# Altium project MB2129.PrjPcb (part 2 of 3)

## Sheet Connectors.SchDoc: Connectors
size A3; Date: Not used; ApprovedBy: Not used; CheckedBy: Not used; Author: Not used; CompanyName: STMicroelectronics; DrawnBy: Not used; Engineer: Not used; Organization: Not used; Address1: Not used; Address2: Not used; Address3: Not used; Address4: Not used; DocumentNumber: 5; Revision: Not used; SheetNumber: 5; SheetTotal: 14
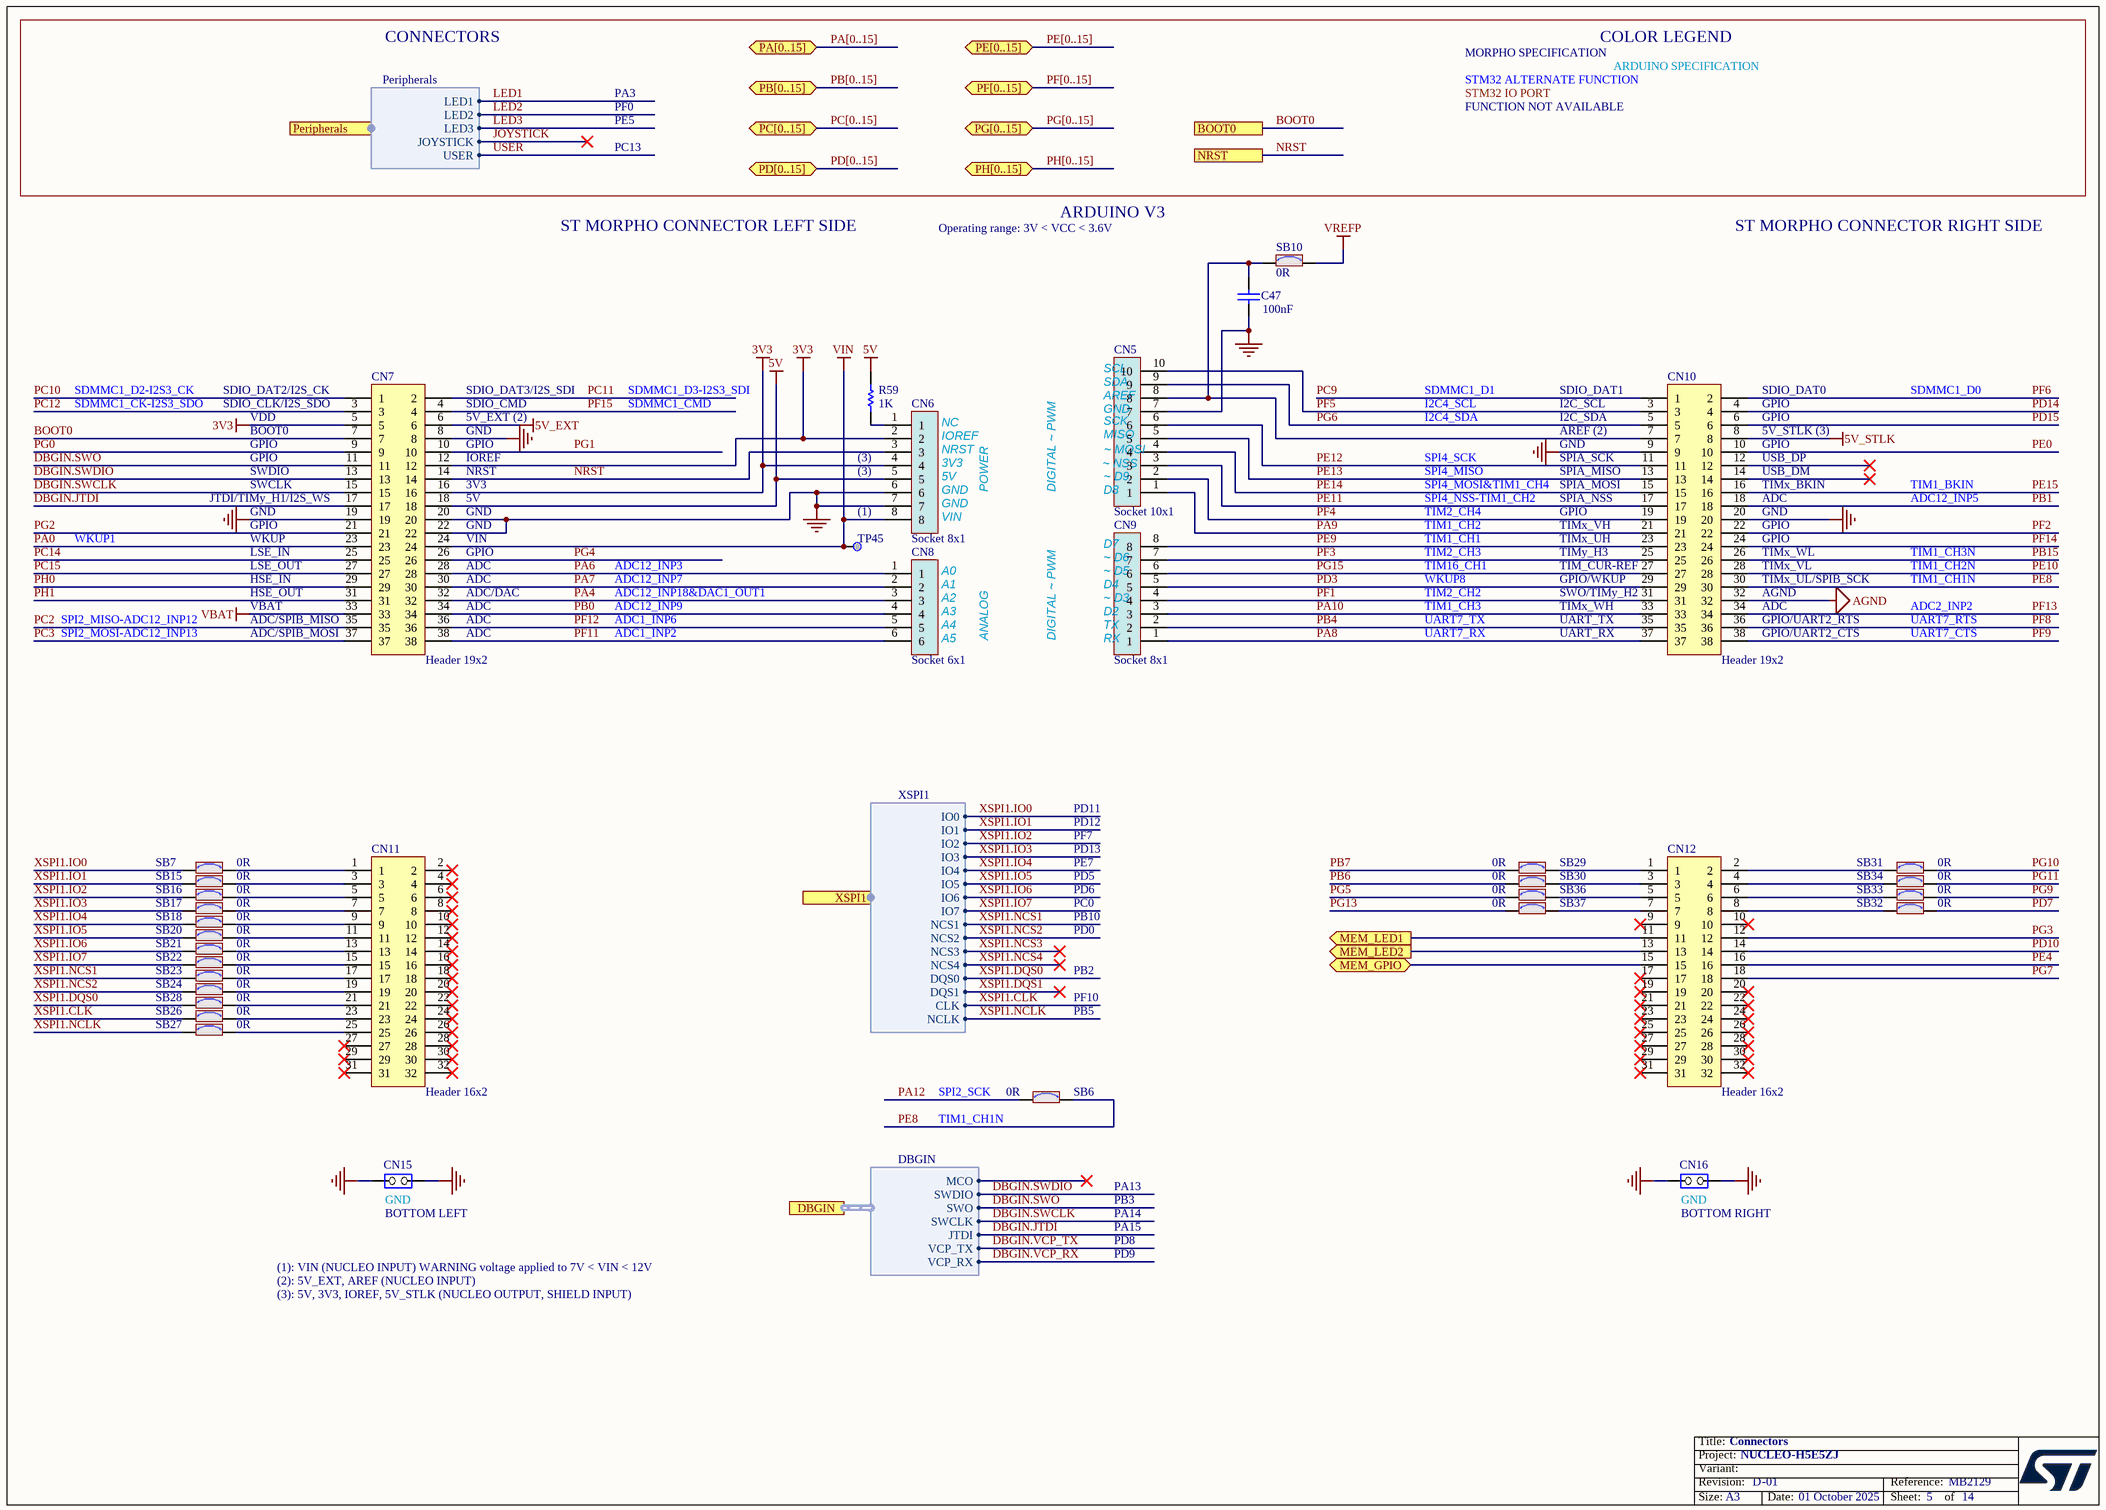
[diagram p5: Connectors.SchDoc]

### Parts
C47  value 100nF  [C0402]  (hidden comment: Capacitor)
CN5  Socket 10x1  [CON_SAMTEC_SSW-110-01-X-S]
CN6  Socket 8x1  [CON_SAMTEC_SSW-108-01-X-S]
CN7  Header 19x2  [CON_SAMTEC_TSW-119-09-X-D]
CN8  Socket 6x1  [CON_SAMTEC_SSW-106-01-X-S]
CN9  Socket 8x1  [CON_SAMTEC_SSW-108-01-X-S]
CN10  Header 19x2  [CON_SAMTEC_TSW-119-09-X-D]
CN11  Header 16x2  [CON_SAMTEC_TSW-116-07-G-D]
CN12  Header 16x2  [CON_SAMTEC_TSW-116-07-G-D]
CN15  Jumper_Header 2x1  [CON_SAMTEC_TSW-102-09-X-S]  (value not drawn)
CN16  Jumper_Header 2x1  [CON_SAMTEC_TSW-102-09-X-S]  (value not drawn)
R59  value 1K  [R0402]  (hidden comment: Resistor)
SB6  value 0R  [SOLDER-BRIDGE_R0603-0R]  (hidden comment: SB_ON)
SB7  value 0R  [SOLDER-BRIDGE_R0603-0R]  (hidden comment: SB_ON)
SB10  value 0R  [SOLDER-BRIDGE_R0402-0R]  (hidden comment: SB_ON)
SB15  value 0R  [SOLDER-BRIDGE_R0603-0R]  (hidden comment: SB_ON)
SB16  value 0R  [SOLDER-BRIDGE_R0603-0R]  (hidden comment: SB_ON)
SB17  value 0R  [SOLDER-BRIDGE_R0603-0R]  (hidden comment: SB_ON)
SB18  value 0R  [SOLDER-BRIDGE_R0603-0R]  (hidden comment: SB_ON)
SB20  value 0R  [SOLDER-BRIDGE_R0603-0R]  (hidden comment: SB_ON)
SB21  value 0R  [SOLDER-BRIDGE_R0603-0R]  (hidden comment: SB_ON)
SB22  value 0R  [SOLDER-BRIDGE_R0603-0R]  (hidden comment: SB_ON)
SB23  value 0R  [SOLDER-BRIDGE_R0603-0R]  (hidden comment: SB_ON)
SB24  value 0R  [SOLDER-BRIDGE_R0603-0R]  (hidden comment: SB_ON)
SB26  value 0R  [SOLDER-BRIDGE_R0603-0R]  (hidden comment: SB_ON)
SB27  value 0R  [SOLDER-BRIDGE_R0603-0R]  (hidden comment: SB_ON)
SB28  value 0R  [SOLDER-BRIDGE_R0603-0R]  (hidden comment: SB_ON)
SB29  value 0R  [SOLDER-BRIDGE_R0603-0R]  (hidden comment: SB_ON)
SB30  value 0R  [SOLDER-BRIDGE_R0603-0R]  (hidden comment: SB_ON)
SB31  value 0R  [SOLDER-BRIDGE_R0603-0R]  (hidden comment: SB_ON)
SB32  value 0R  [SOLDER-BRIDGE_R0603-0R]  (hidden comment: SB_ON)
SB33  value 0R  [SOLDER-BRIDGE_R0603-0R]  (hidden comment: SB_ON)
SB34  value 0R  [SOLDER-BRIDGE_R0603-0R]  (hidden comment: SB_ON)
SB36  value 0R  [SOLDER-BRIDGE_R0603-0R]  (hidden comment: SB_ON)
SB37  value 0R  [SOLDER-BRIDGE_R0603-0R]  (hidden comment: SB_ON)
TP45  Test Point  [TP_SMD_0-6MM]  (value not drawn)  (no BOM)

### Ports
BOOT0, DBGIN (harness DBGIN), MEM_GPIO (bidir), MEM_LED1 (out), MEM_LED2 (out), NRST, PA[0..15] (bidir), PB[0..15] (bidir), PC[0..15] (bidir), PD[0..15] (bidir), PE[0..15] (bidir), Peripherals (harness Peripherals), PF[0..15] (bidir), PG[0..15] (bidir), PH[0..15] (bidir), XSPI1 (harness XSPI1)

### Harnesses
Peripherals: LED1, LED2, USER, LED3, JOYSTICK
XSPI1: IO0, IO1, IO2, IO3, IO4, IO5, IO6, IO7, NCS1, NCS2, DQS0, CLK, NCLK, NCS3, NCS4, DQS1
DBGIN: SWDIO, SWO, VCP_TX, SWCLK, VCP_RX, MCO, JTDI

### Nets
3V3: CN6.2 CN6.4 CN7.5 CN7.12 CN7.16
5V: CN6.5 CN7.18 R59.2
5V_EXT: CN7.6
5V_STLK: CN10.8
AGND: CN10.32
GND: C47.2 CN5.7 CN6.6 CN6.7 CN7.8 CN7.19 CN7.20 CN7.22 CN10.9 CN10.20 CN15.1(COMMON) CN15.2(NO) CN16.1(COMMON) CN16.2(NO)
VBAT: CN7.33
VIN: CN6.8 CN7.24 TP45.1
VREFP: SB10.1
BOOT0: CN7.7 ; port BOOT0
DBGIN.JTDI: CN7.17 ; port DBGIN.JTDI
DBGIN.SWCLK: CN7.15 ; port DBGIN.SWCLK
DBGIN.SWDIO: CN7.13 ; port DBGIN.SWDIO
DBGIN.SWO: CN7.11 ; port DBGIN.SWO
MEM_GPIO: CN12.15 ; port MEM_GPIO
MEM_LED1: CN12.11 ; port MEM_LED1
MEM_LED2: CN12.13 ; port MEM_LED2
NRST: CN6.3 CN7.14 ; port NRST
PA0: CN7.23
PA4: CN7.32 CN8.3
PA6: CN7.28 CN8.1
PA7: CN7.30 CN8.2
PA8: CN9.1 CN10.37
PA9: CN5.1 CN10.21
PA10: CN9.3 CN10.33
PA12: SB6.1
PB0: CN7.34 CN8.4
PB1: CN10.18
PB4: CN9.2 CN10.35
PB6: SB30.1
PB7: SB29.1
PB15: CN10.26
PC2: CN7.35
PC3: CN7.37
PC9: CN10.1
PC10: CN7.1
PC11: CN7.2
PC12: CN7.3
PC14: CN7.25
PC15: CN7.27
PD3: CN9.5 CN10.29
PD7: SB32.1
PD10: CN12.14
PD14: CN10.4
PD15: CN10.6
PE0: CN10.10
PE4: CN12.16
PE8: CN10.30 SB6.2
PE9: CN9.8 CN10.23
PE10: CN10.28
PE11: CN5.3 CN10.17
PE12: CN5.6 CN10.11
PE13: CN5.5 CN10.13
PE14: CN5.4 CN10.15
PE15: CN10.16
PF1: CN9.4 CN10.31
PF2: CN10.22
PF3: CN9.7 CN10.25
PF4: CN5.2 CN10.19
PF5: CN5.10 CN10.3
PF6: CN10.2
PF8: CN10.36
PF9: CN10.38
PF11: CN7.38 CN8.6
PF12: CN7.36 CN8.5
PF13: CN10.34
PF14: CN10.24
PF15: CN7.4
PG0: CN7.9
PG1: CN7.10
PG2: CN7.21
PG3: CN12.12
PG4: CN7.26
PG5: SB36.1
PG6: CN5.9 CN10.5
PG7: CN12.18
PG9: SB33.1
PG10: SB31.1
PG11: SB34.1
PG13: SB37.1
PG15: CN9.6 CN10.27
PH0: CN7.29
PH1: CN7.31
XSPI1.CLK: SB26.1 ; port XSPI1.CLK
XSPI1.DQS0: SB28.1 ; port XSPI1.DQS0
XSPI1.IO0: SB7.1 ; port XSPI1.IO0
XSPI1.IO1: SB15.1 ; port XSPI1.IO1
XSPI1.IO2: SB16.1 ; port XSPI1.IO2
XSPI1.IO3: SB17.1 ; port XSPI1.IO3
XSPI1.IO4: SB18.1 ; port XSPI1.IO4
XSPI1.IO5: SB20.1 ; port XSPI1.IO5
XSPI1.IO6: SB21.1 ; port XSPI1.IO6
XSPI1.IO7: SB22.1 ; port XSPI1.IO7
XSPI1.NCLK: SB27.1 ; port XSPI1.NCLK
XSPI1.NCS1: SB23.1 ; port XSPI1.NCS1
XSPI1.NCS2: SB24.1 ; port XSPI1.NCS2
NetC47_1: C47.1 CN5.8 CN10.7 SB10.2
NetCN6_1: CN6.1 R59.1
NetCN11_1: CN11.1 SB7.2
NetCN11_3: CN11.3 SB15.2
NetCN11_5: CN11.5 SB16.2
NetCN11_7: CN11.7 SB17.2
NetCN11_9: CN11.9 SB18.2
NetCN11_11: CN11.11 SB20.2
NetCN11_13: CN11.13 SB21.2
NetCN11_15: CN11.15 SB22.2
NetCN11_17: CN11.17 SB23.2
NetCN11_19: CN11.19 SB24.2
NetCN11_21: CN11.21 SB28.2
NetCN11_23: CN11.23 SB26.2
NetCN11_25: CN11.25 SB27.2
NetCN12_1: CN12.1 SB29.2
NetCN12_2: CN12.2 SB31.2
NetCN12_3: CN12.3 SB30.2
NetCN12_4: CN12.4 SB34.2
NetCN12_5: CN12.5 SB36.2
NetCN12_6: CN12.6 SB33.2
NetCN12_7: CN12.7 SB37.2
NetCN12_8: CN12.8 SB32.2

Not connected (* = marked no-connect by the designer): CN10 12* 14*; CN11 2* 4* 6* 8* 10* 12* 14* 16* 18* 20* 22* 24* 26* 27* 28* 29* 30* 31* 32*; CN12 9* 10* 17* 19* 20* 21* 22* 23* 24* 25* 26* 27* 28* 29* 30* 31* 32*

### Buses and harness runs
bus PA[0..15] = port PA[0..15]
bus PB[0..15] = port PB[0..15]
bus PC[0..15] = port PC[0..15]
bus PD[0..15] = port PD[0..15]
bus PE[0..15] = port PE[0..15]
bus PF[0..15] = port PF[0..15]
bus PG[0..15] = port PG[0..15]
bus PH[0..15] = port PH[0..15]

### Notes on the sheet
- CONNECTORS
- COLOR LEGEND
- PA3
- PF0
- MORPHO SPECIFICATION
- STM32 ALTERNATE FUNCTION
- STM32 IO PORT
- FUNCTION NOT AVAILABLE
- ARDUINO SPECIFICATION
- PE5
- PC13
- ST MORPHO CONNECTOR LEFT SIDE
- Operating range: 3V < VCC < 3.6V
- ARDUINO V3
- ST MORPHO CONNECTOR RIGHT SIDE
- (near CN5) SDA
- (near CN5) SCL
- SDMMC1_CK-I2S3_SDO
- SDMMC1_D2-I2S3_CK
- (near CN7) SDIO_DAT2/I2S_CK
- (near CN7) SDIO_CLK/I2S_SDO
- BOOT0
- GPIO
- VDD
- (near CN7) SDIO_CMD
- (near CN7) GPIO
- (near CN7) 5V_EXT (2)
- (near CN7) GND
- (near CN7) SDIO_DAT3/I2S_SDI
- SDMMC1_CMD
- SDMMC1_D3-I2S3_SDI
- (near CN6) IOREF
- (near CN6) NRST
- (near CN6) NC
- (near CN5) SCK
- (near CN5) MISO
- (near CN5) AREF
- (near CN5) GND
- (near CN5) ~ MOSI
- I2C4_SDA
- I2C4_SCL
- SDMMC1_D1
- (near CN10) SDIO_DAT1
- I2C_SCL
- I2C_SDA
- AREF (2)
- GND
- (near CN10) SDIO_DAT0
- (near CN10) GPIO
- (near CN10) 5V_STLK (3)
- SDMMC1_D0
- (near CN7) JTDI/TIMy_H1/I2S_WS
- SWDIO
- SWCLK
- (near CN7) IOREF
- (near CN7) 3V3
- (near CN7) 5V
- (near CN7) NRST
- (1)
- (3)
- (near CN6) 3V3
- (near CN6) 5V
- (near CN6) GND
- (near CN6) VIN
- POWER
- DIGITAL ~ PWM
- (near CN5) ~ NSS
- (near CN5) D8
- (near CN5) ~ D9
- SPI4_MISO
- SPI4_MOSI&TIM1_CH4
- SPI4_NSS-TIM1_CH2
- TIM2_CH4
- SPI4_SCK
- SPIA_SCK
- (near CN10) SPIA_MISO
- (near CN10) SPIA_MOSI
- SPIA_NSS
- (near CN10) USB_DP
- (near CN10) USB_DM
- (near CN10) TIMx_BKIN
- (near CN10) ADC
- (near CN10) GND
- ADC12_INP5
- TIM1_BKIN
- WKUP1
- WKUP
- LSE_IN
- LSE_OUT
- HSE_IN
- (near CN7) VIN
- (near CN7) ADC
- ADC12_INP7
- ADC12_INP3
- (near CN8) A0
- (near CN8) A1
- (near CN9) D4
- (near CN9) ~ D5
- (near CN9) ~ D6
- D7
- TIM1_CH2
- TIM1_CH1
- TIM2_CH3
- WKUP8
- TIM16_CH1
- (near CN10) TIM_CUR-REF
- TIMx_VH
- TIMx_UH
- TIMy_H3
- (near CN10) GPIO/WKUP
- (near CN10) TIMx_WL
- (near CN10) TIMx_VL
- (near CN10) TIMx_UL/SPIB_SCK
- TIM1_CH1N
- TIM1_CH2N
- TIM1_CH3N
- SPI2_MOSI-ADC12_INP13
- SPI2_MISO-ADC12_INP12
- HSE_OUT
- (near CN7) ADC/SPIB_MISO
- (near CN7) ADC/SPIB_MOSI
- VBAT
- (near CN7) ADC/DAC
- ADC1_INP2
- ADC1_INP6
- ADC12_INP9
- ADC12_INP18&DAC1_OUT1
- (near CN8) A2
- (near CN8) A3
- (near CN8) A4
- (near CN8) A5
- ANALOG
- (near CN9) RX
- (near CN9) TX
- (near CN9) D2
- (near CN9) ~ D3
- TIM2_CH2
- TIM1_CH3
- UART7_TX
- UART7_RX
- UART_TX
- UART_RX
- (near CN10) SWO/TIMy_H2
- TIMx_WH
- (near CN10) AGND
- (near CN10) GPIO/UART2_RTS
- (near CN10) GPIO/UART2_CTS
- UART7_CTS
- UART7_RTS
- ADC2_INP2
- PD11
- PD12
- PF7
- PD13
- PE7
- PD5
- PD6
- PC0
- PB10
- PD0
- PB2
- PF10
- PB5
- (near SB6) TIM1_CH1N
- (near SB6) SPI2_SCK
- PA13
- (near CN15) GND
- (near CN15) BOTTOM LEFT
- PB3
- PA14
- PD8
- PD9
- PA15
- (near CN16) GND
- (near CN16) BOTTOM RIGHT
- (1): VIN (NUCLEO INPUT) WARNING voltage applied to 7V < VIN < 12V
- (2): 5V_EXT, AREF (NUCLEO INPUT)
- (3): 5V, 3V3, IOREF, 5V_STLK (NUCLEO OUTPUT, SHIELD INPUT)

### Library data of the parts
C47 = MCD-00006: Capacitor, MLCC, 100nF, 16V, X7R, +/-10%, 0402, T=0.5mm; Manufacturer_Part_Number: CC0402KRX7R7BB104; Manufacturer: YAGEO; Part_Preference: Recommended; Partial_Alternate_Internal_Part_Number: MCD-03299; Order_Code_RS: 616-9701; Component_Country_Of_Origin: China; ShowFields: YES; ID: 2474
CN5 = MCD-02080: Socket, 10x1, 2.54mm, VR, TH, T=8.51/2.64mm; Part_Type: Connector; Part_Preference: Recommended; Manufacturer: SAMTEC; Manufacturer_Part_Number: SSW-110-01-G-S; Order_Code_RS: 765-5736; Component_Country_Of_Origin: China, Costa Rica, Malaysia, United States, Vietnam; ShowFields: YES; ID: 4180
CN6 CN9 = MCD-01743: Socket, 8x1, 2.54mm, VR, TH, T=8.51/2.64mm; Part_Type: Connector; Part_Preference: Recommended; Manufacturer: SAMTEC; Manufacturer_Part_Number: SSW-108-01-G-S; Order_Code_RS: 765-5698; Component_Country_Of_Origin: China, Costa Rica, Malaysia, United States, Vietnam; ShowFields: YES; ID: 3843
CN7 CN10 = MCD-00213: Header, 19x2, 2.54mm, VR, TH, T=5.84mm/10.16mm; Part_Type: Connector; Part_Preference: Recommended; Manufacturer: SAMTEC; Manufacturer_Part_Number: TSW-119-09-G-D; Component_Country_Of_Origin: China, Costa Rica, Malaysia, United States, Vietnam; ShowFields: YES; ID: 2656
CN8 = MCD-02079: Socket, 6x1, 2.54mm, VR, TH, T=8.51/2.64mm; Part_Type: Connector; Part_Preference: Recommended; Manufacturer: SAMTEC; Manufacturer_Part_Number: SSW-106-01-G-S; Order_Code_RS: 765-5666; Component_Country_Of_Origin: China, Costa Rica, Malaysia, United States, Vietnam; ShowFields: YES; ID: 4179
CN11 CN12 = MCD-02536: Header, 16x2, 2.54mm, VR, TH, T=5.84mm/8.38mm; Part_Type: Connector; Part_Preference: Recommended; Manufacturer: SAMTEC; Manufacturer_Part_Number: TSW-116-07-G-D; Order_Code_RS: 180-2921; ShowFields: YES; ID: 4642
CN15 CN16 = MCD-00214: Header, 2x1, 2.54mm, VR, TH, T=5.84mm/10.16mm; Manufacturer_Part_Number: TSW-102-09-G-S; Manufacturer: SAMTEC; Part_Type: Connector; Part_Preference: Recommended; Full_Alternate_Internal_Part_Number: MCD-02393; Partial_Alternate_Internal_Part_Number: MCD-03591; Order_Code_RS: 180-3129; Component_Country_Of_Origin: China, Costa Rica, Malaysia, United States, Vietnam; ShowFields: YES; ID: 2652; Alternate_EMS: A
R59 = MCD-00061: Resistor, 1K, 0402, +/-1%,1/16W; Manufacturer_Part_Number: RC0402FR-071KL; Manufacturer: YAGEO; Part_Preference: Recommended; Component_Country_Of_Origin: China; ShowFields: YES; ID: 2532
SB6 SB7 SB15-SB18 SB20-SB24 SB26-SB34 SB36 SB37 = MCD-00071: Resistor, 0R, SB0603, 5%, 0.1W; Manufacturer_Part_Number: RC0603JR-070RL; Manufacturer: YAGEO; Part_Preference: Recommended; Manufacturer_HQ_COO: Unknown; Order_Code_RS: 199-5647; Component_Country_Of_Origin: China; ShowFields: YES; ID: 2521
SB10 = MCD-01618: Resistor, 0R, SB0402, 5%, 0.063W; Manufacturer_Part_Number: RC0402JR-070RL; Manufacturer: YAGEO; Part_Preference: Recommended; ShowFields: YES; ID: 3718; Order_Code_RS: 618-5804; Component_Country_Of_Origin: China
TP45 = MCD-00631: Test Point 0.6mm; Part_Type: Misc; Part_Preference: Recommended; ShowFields: YES; ID: 3108; Component_Country_Of_Origin: Unknown

## Sheet MCU_Power.SchDoc: MCU Power
size A4; Date: Not used; ApprovedBy: Not used; CheckedBy: Not used; Author: Not used; CompanyName: STMicroelectronics; DrawnBy: Not used; Engineer: Not used; Organization: Not used; Address1: Not used; Address2: Not used; Address3: Not used; Address4: Not used; DocumentNumber: 4; Revision: Not used; SheetNumber: 4; SheetTotal: 14
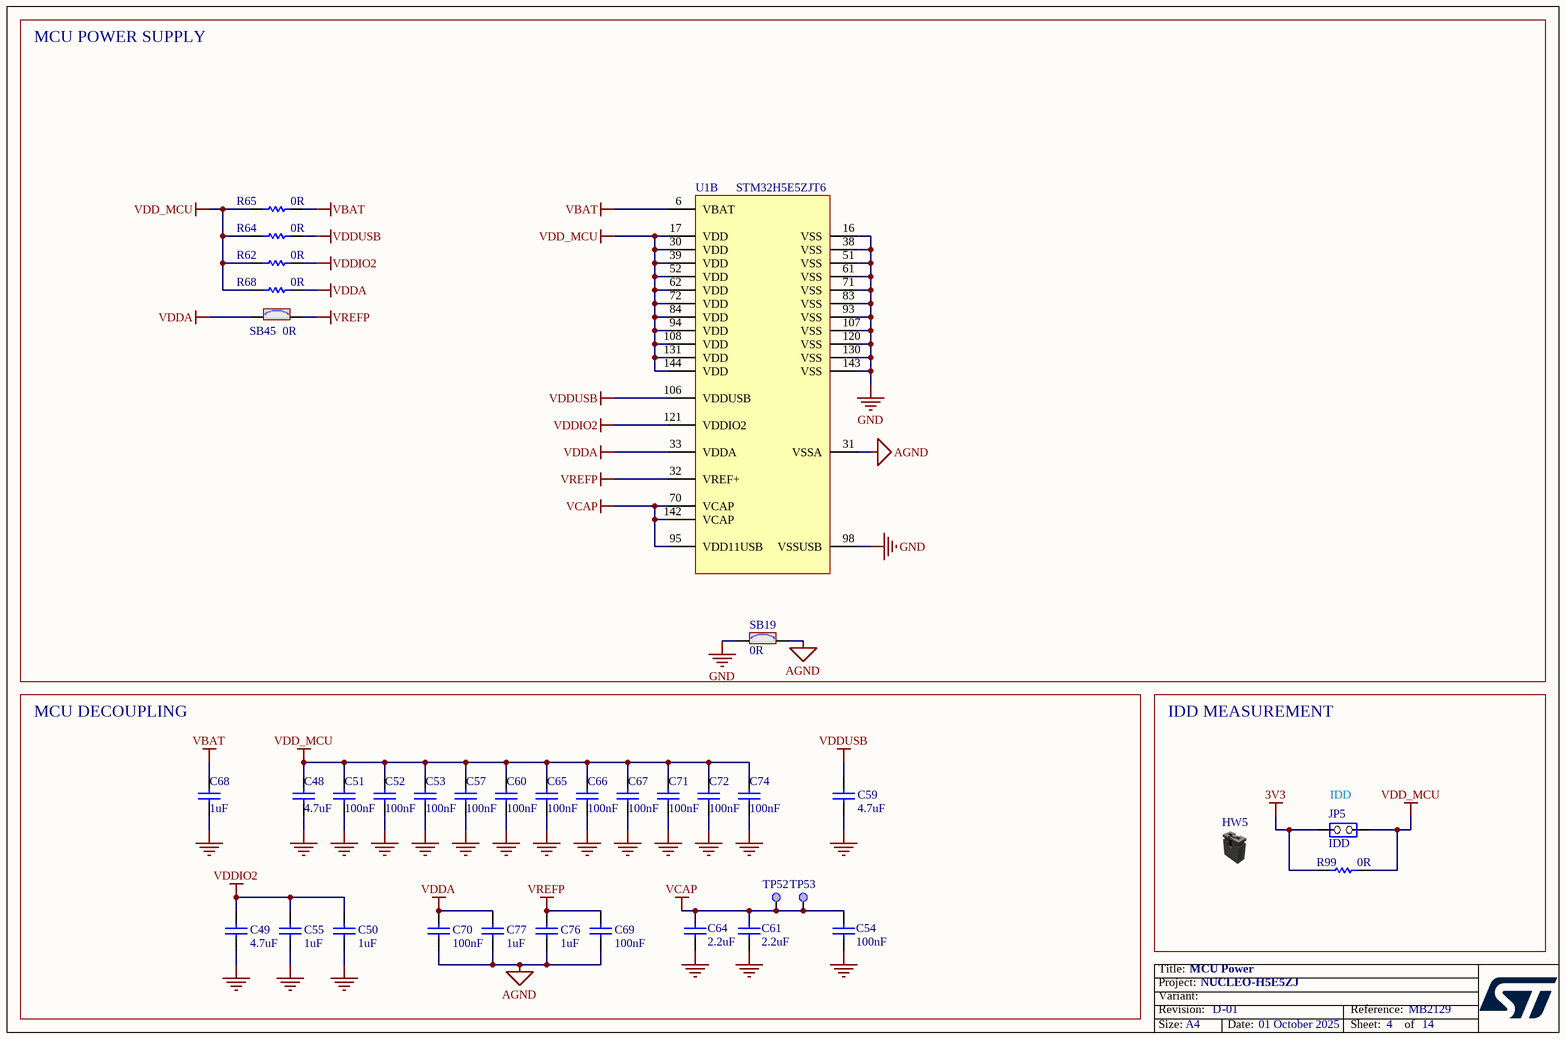
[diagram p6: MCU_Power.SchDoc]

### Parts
C48  value 4.7uF  [C0603_H0P8]  (hidden comment: Capacitor)
C49  value 4.7uF  [C0603_H0P8]  (hidden comment: Capacitor)
C50  value 1uF  [C0402]  (hidden comment: Capacitor)
C51  value 100nF  [C0402_MURATA_GRM155_H0P5]  (hidden comment: Capacitor)
C52  value 100nF  [C0402_MURATA_GRM155_H0P5]  (hidden comment: Capacitor)
C53  value 100nF  [C0402_MURATA_GRM155_H0P5]  (hidden comment: Capacitor)
C54  value 100nF  [C0402_MURATA_GRM155_H0P5]  (hidden comment: Capacitor)
C55  value 1uF  [C0402]  (hidden comment: Capacitor)
C57  value 100nF  [C0402_MURATA_GRM155_H0P5]  (hidden comment: Capacitor)
C59  value 4.7uF  [C0603_H0P8]  (hidden comment: Capacitor)
C60  value 100nF  [C0402_MURATA_GRM155_H0P5]  (hidden comment: Capacitor)
C61  value 2.2uF  [C0402_H0P5]  (hidden comment: Capacitor)
C64  value 2.2uF  [C0402_H0P5]  (hidden comment: Capacitor)
C65  value 100nF  [C0402_MURATA_GRM155_H0P5]  (hidden comment: Capacitor)
C66  value 100nF  [C0402_MURATA_GRM155_H0P5]  (hidden comment: Capacitor)
C67  value 100nF  [C0402_MURATA_GRM155_H0P5]  (hidden comment: Capacitor)
C68  value 1uF  [C0402]  (hidden comment: Capacitor)
C69  value 100nF  [C0402]  (hidden comment: Capacitor)
C70  value 100nF  [C0402]  (hidden comment: Capacitor)
C71  value 100nF  [C0402_MURATA_GRM155_H0P5]  (hidden comment: Capacitor)
C72  value 100nF  [C0402_MURATA_GRM155_H0P5]  (hidden comment: Capacitor)
C74  value 100nF  [C0402_MURATA_GRM155_H0P5]  (hidden comment: Capacitor)
C76  value 1uF  [C0402]  (hidden comment: Capacitor)
C77  value 1uF  [C0402]  (hidden comment: Capacitor)
HW5  Shunt Black 2.54mm  (value not drawn)  (mechanical)
JP5  IDD  [CON_SAMTEC_TSW-102-07-G-S]
R62  value 0R  [R0603]  (hidden comment: Resistor)
R64  value 0R  [R0603]  (hidden comment: Resistor)
R65  value 0R  [R0603]  (hidden comment: Resistor)
R68  value 0R  [R0603]  (hidden comment: Resistor)
R99  value 0R  [R0603]  (hidden comment: Resistor)
SB19  value 0R  [SOLDER-BRIDGE_R0603-0R]  (hidden comment: SB_ON)
SB45  value 0R  [SOLDER-BRIDGE_R0402-0R]  (hidden comment: SB_ON)
TP52  Test Point  [TP_SMD_0-6MM]  (value not drawn)  (no BOM)
TP53  Test Point  [TP_SMD_0-6MM]  (value not drawn)  (no BOM)
U1  value STM32H5E5ZJT6  [ICC_LQFP144_20X20_P050_SOCKET_YAMAICHI_IC149-144-145-B5_NM]  (hidden comment: IC_STM32H5E5ZJT6)  (part B of 4)

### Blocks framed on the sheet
MCU POWER SUPPLY: R62 R64 R65 R68 SB19 SB45 U1
MCU DECOUPLING: C48-C55 C57 C59-C61 C64-C72 C74 C76 C77 TP52 TP53
IDD MEASUREMENT: HW5 JP5 R99

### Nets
3V3: JP5.1(COMMON) R99.1
AGND: C69.1 C70.1 C76.1 C77.1 SB19.2 U1.31(VSSA)
GND: C48.1 C49.1 C50.1 C51.1 C52.1 C53.1 C54.2 C55.1 C57.1 C59.1 C60.1 C61.2 C64.2 C65.1 C66.1 C67.1 C68.1 C71.1 C72.1 C74.1 SB19.1 U1.16(VSS) U1.38(VSS) U1.51(VSS) U1.61(VSS) U1.71(VSS) U1.83(VSS) U1.93(VSS) U1.98(VSSUSB) U1.107(VSS) U1.120(VSS) U1.130(VSS) U1.143(VSS)
VBAT: C68.2 R65.2 U1.6(VBAT)
VCAP: C54.1 C61.1 C64.1 TP52.1 TP53.1 U1.70(VCAP) U1.95(VDD11USB) U1.142(VCAP)
VDD_MCU: C48.2 C51.2 C52.2 C53.2 C57.2 C60.2 C65.2 C66.2 C67.2 C71.2 C72.2 C74.2 JP5.2(NO) R62.1 R64.1 R65.1 R68.1 R99.2 U1.17(VDD) U1.30(VDD) U1.39(VDD) U1.52(VDD) U1.62(VDD) U1.72(VDD) U1.84(VDD) U1.94(VDD) U1.108(VDD) U1.131(VDD) U1.144(VDD)
VDDA: C70.2 C77.2 R68.2 SB45.2 U1.33(VDDA)
VDDIO2: C49.2 C50.2 C55.2 R62.2 U1.121(VDDIO2)
VDDUSB: C59.2 R64.2 U1.106(VDDUSB)
VREFP: C69.2 C76.2 SB45.1 U1.32(VREF+)

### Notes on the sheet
- (near JP5) IDD

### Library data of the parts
C48 C49 C59 = MCD-03342: Capacitor, MLCC, 4.7uF, 10V, X5R, +/-20%, 0603, T=0.8mm; Part_Preference: Recommended; Manufacturer: YAGEO; Manufacturer_Part_Number: CC0603MRX5R6BB475; Partial_Alternate_Internal_Part_Number: MCD-01721; Component_Country_Of_Origin: China, Taiwan; ShowFields: YES; ID: 5458
C50 C55 C68 C76 C77 = MCD-01722: Capacitor, MLCC, 1uF, 10V, X5R, +/-10%, 0402, T=0.5mm; Part_Preference: Recommended; Manufacturer: YAGEO; Manufacturer_Part_Number: CC0402KRX5R6BB105; Component_Country_Of_Origin: China; ShowFields: YES; ID: 3822
C51-C54 C57 C60 C65-C67 C71 C72 C74 = MCD-04435: Capacitor, MLCC, 100nF, 10V, X5R, +/-10%, 0402, T=0.5mm; Part_Preference: Recommended; Manufacturer: MURATA; Manufacturer_Part_Number: GRM155R61A104KA01; Component_Country_Of_Origin: Japan, China, Philippines, Singapore; ShowFields: YES; ID: 6551
C61 C64 = MCD-04261: Capacitor, MLCC, 2.2uF, 10V, X5R, +/-10%, 0402, T=0.5mm; Part_Preference: Recommended; Manufacturer: YAGEO; Manufacturer_Part_Number: CC0402KPX5R6BB225; Component_Country_Of_Origin: China; ShowFields: YES; ID: 6377
C69 C70 = MCD-00006: Capacitor, MLCC, 100nF, 16V, X7R, +/-10%, 0402, T=0.5mm; Part_Preference: Recommended; Manufacturer: YAGEO; Manufacturer_Part_Number: CC0402KRX7R7BB104; Partial_Alternate_Internal_Part_Number: MCD-03299; Order_Code_RS: 9402047; Component_Country_Of_Origin: China; ShowFields: YES; ID: 2474
HW5 = MCD-00043: SHUNT 2.54mm BLACK; Part_Type: Misc; Part_Preference: Recommended; Manufacturer: SAMTEC; Full_Alternate_Internal_Part_Number: MCD-02388; Partial_Alternate_Internal_Part_Number: MCD-01849; Value: SNT-100-BK-G; Component_Country_Of_Origin: China, Costa Rica, Malaysia, United States, Vietnam; ShowFields: YES; ID: 2551; Alternate_EMS: A
JP5 = MCD-00045: Header, 2x1, 2.54mm, VR, TH, T=5.84mm/2.54mm; Part_Type: Connector; Part_Preference: Recommended; Manufacturer: SAMTEC; Manufacturer_Part_Number: TSW-102-07-G-S; Full_Alternate_Internal_Part_Number: MCD-02390; Partial_Alternate_Internal_Part_Number: MCD-02957, MCD-03720; Order_Code_RS: 2505044; Component_Country_Of_Origin: China, Costa Rica, Malaysia, USA, Vietnam; ShowFields: YES; ID: 2545
R62 R64 R65 R68 = MCD-00181: Resistor, 0R, 0603, +/- 0.5mR, 1/4W; Part_Preference: Recommended; Manufacturer: ROHM SEMICONDUCTOR; Manufacturer_Part_Number: PMR03EZPJ000; Component_Country_Of_Origin: Philippines, Thailand°°; ShowFields: YES; ID: 2691
R99 = MCD-00056: Resistor, 0R, 0603, +/-5%, 1/10W; Part_Preference: Recommended; Manufacturer: YAGEO; Manufacturer_Part_Number: RC0603JR-070RL; Order_Code_RS: 9233130RL; Component_Country_Of_Origin: China; ShowFields: YES; ID: 2536
SB19 = MCD-00071: as SB6 on sheet Connectors
SB45 = MCD-01618: Resistor, 0R, SB0402, 5%, 0.063W; Manufacturer_Part_Number: RC0402JR-070RL; Manufacturer: YAGEO; Part_Preference: Recommended; Order_Code_RS: 618-5804; Component_Country_Of_Origin: China; ID: 3718; ShowFields: YES
TP52 TP53 = MCD-00631: as TP45 on sheet Connectors
U1 = MCD-04286: MCU, ARM Cortex-M33 32-bit, 4MB Flash, 1.5MB RAM, No Crypto; Part_Type: IC; Part_Preference: Recommended; Manufacturer: STMICROELECTRONICS; Component_Country_Of_Origin: Unknown; ShowFields: YES; ID: 6402

## Sheet MCU_IOs.SchDoc: MCU IOs
size A4; Date: Not used; ApprovedBy: Not used; CheckedBy: Not used; Author: Not used; CompanyName: STMicroelectronics; DrawnBy: Not used; Engineer: Not used; Organization: Not used; Address1: Not used; Address2: Not used; Address3: Not used; Address4: Not used; DocumentNumber: 3; Revision: Not used; SheetNumber: 3; SheetTotal: 14
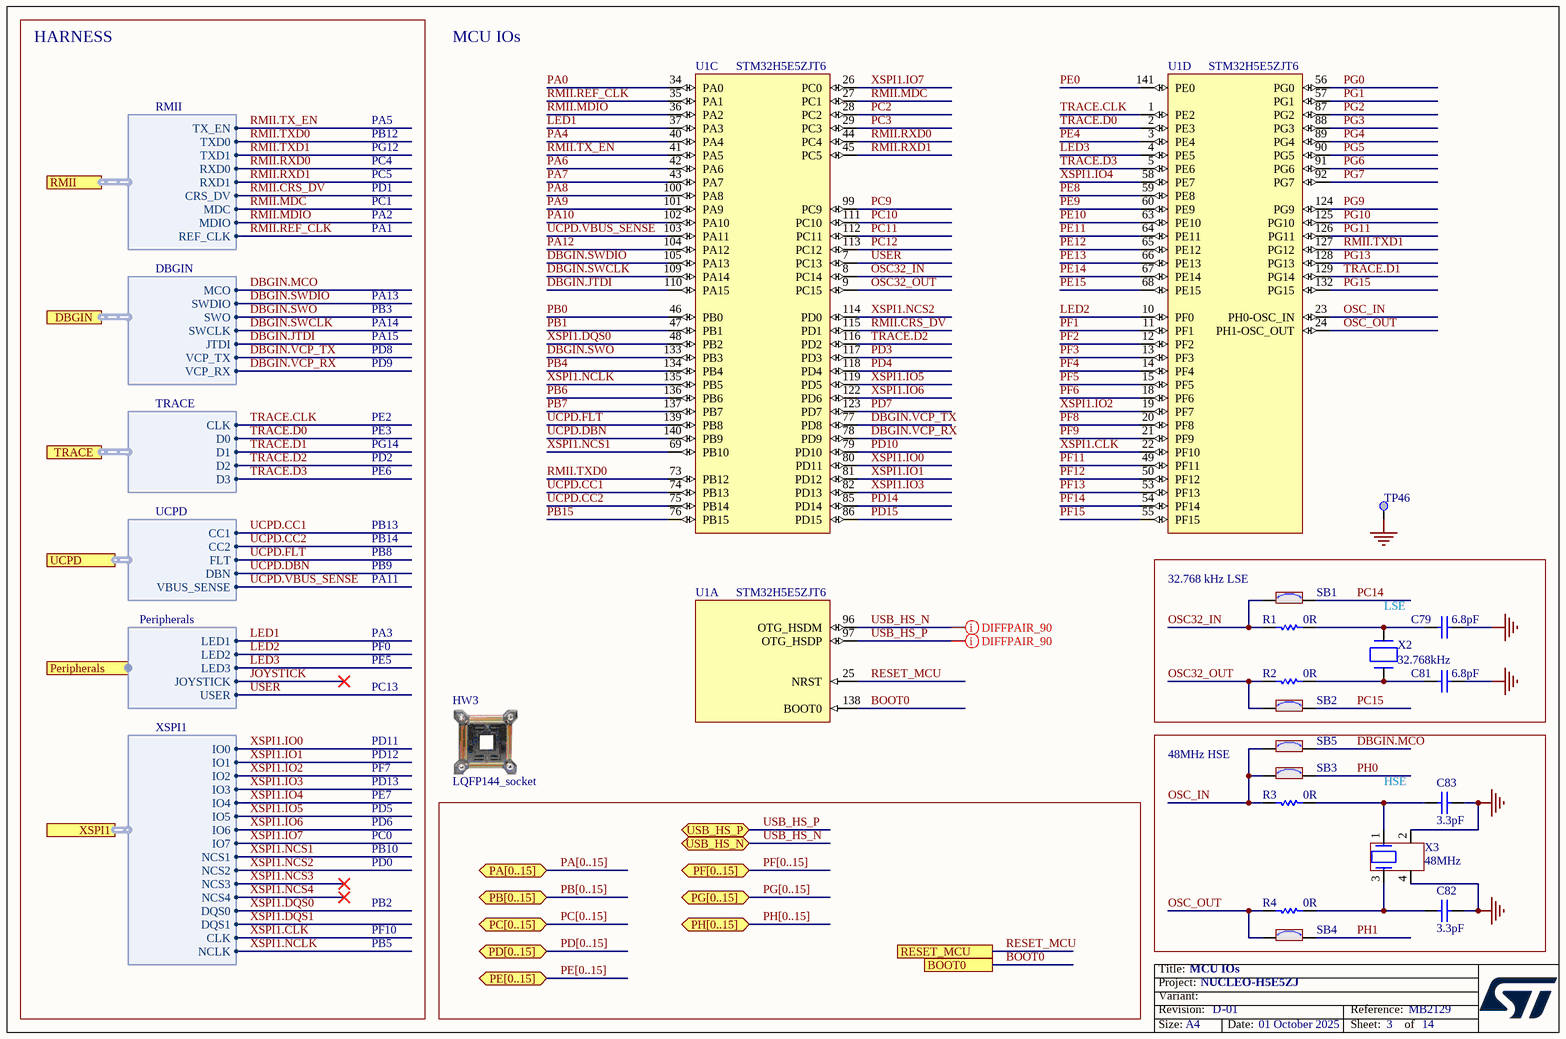
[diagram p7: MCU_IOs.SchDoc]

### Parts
C79  value 6.8pF  [C0402]  (hidden comment: Capacitor)
C81  value 6.8pF  [C0402]  (hidden comment: Capacitor)
C82  value 3.3pF  [C0402]  (hidden comment: Capacitor)
C83  value 3.3pF  [C0402]  (hidden comment: Capacitor)
HW3  value LQFP144_socket  (hidden comment: SOCKET_LQFP144)  (mechanical)
R1  value 0R  [R0402]  (hidden comment: Resistor)
R2  value 0R  [R0402]  (hidden comment: Resistor)
R3  value 0R  [R0402]  (hidden comment: Resistor)
R4  value 0R  [R0402]  (hidden comment: Resistor)
SB1  SB_ON  [SOLDER-BRIDGE_R0603-0R]  (value not drawn)
SB2  SB_ON  [SOLDER-BRIDGE_R0603-0R]  (value not drawn)
SB3  SB_ON  [SOLDER-BRIDGE_R0603-0R]  (value not drawn)
SB4  SB_ON  [SOLDER-BRIDGE_R0603-0R]  (value not drawn)
SB5  SB_ON  [SOLDER-BRIDGE_R0603-0R]  (value not drawn)
TP46  Test Point  [TP_SMD_0-6MM]  (value not drawn)  (no BOM)
U1  value STM32H5E5ZJT6  [ICC_LQFP144_20X20_P050_SOCKET_YAMAICHI_IC149-144-145-B5_NM]  (hidden comment: IC_STM32H5E5ZJT6)  (parts A,C,D of 4)
X2  value 32.768kHz  [CRY_NX1610SE_2P]  (hidden comment: XTAL_2_PINS)
X3  value 48MHz  [CRY_NX1612SA_4P]  (hidden comment: XTAL_4_PINS)

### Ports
BOOT0, DBGIN (harness DBGIN), PA[0..15] (bidir), PB[0..15] (bidir), PC[0..15] (bidir), PD[0..15] (bidir), PE[0..15] (bidir), Peripherals (harness Peripherals), PF[0..15] (bidir), PG[0..15] (bidir), PH[0..15] (bidir), RESET_MCU, RMII (harness RMII), TRACE (harness TRACE), UCPD (harness UCPD), USB_HS_N (bidir), USB_HS_P (bidir), XSPI1 (harness XSPI1)

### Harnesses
Peripherals: LED1, LED2, USER, LED3, JOYSTICK
TRACE: CLK, D2, D0, D3, D1
RMII: TX_EN, TXD0, TXD1, RXD0, RXD1, CRS_DV, MDC, MDIO, REF_CLK
UCPD: CC1, CC2, DBN, VBUS_SENSE, FLT
DBGIN: SWDIO, SWO, VCP_TX, SWCLK, VCP_RX, MCO, JTDI
XSPI1: IO0, IO1, IO2, IO3, IO4, IO5, IO6, IO7, NCS1, NCS2, DQS0, CLK, NCLK, NCS3, NCS4, DQS1

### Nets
GND: C79.1 C81.1 C82.2 C83.2 TP46.1 X3.2 X3.4
BOOT0: U1.138(BOOT0) ; port BOOT0
DBGIN.JTDI: U1.110(PA15) ; port DBGIN.JTDI
DBGIN.MCO: SB5.2 ; port DBGIN.MCO
DBGIN.SWCLK: U1.109(PA14) ; port DBGIN.SWCLK
DBGIN.SWDIO: U1.105(PA13) ; port DBGIN.SWDIO
DBGIN.SWO: U1.133(PB3) ; port DBGIN.SWO
DBGIN.VCP_RX: U1.78(PD9) ; port DBGIN.VCP_RX
DBGIN.VCP_TX: U1.77(PD8) ; port DBGIN.VCP_TX
LED1: U1.37(PA3) ; port Peripherals.LED1
LED2: U1.10(PF0) ; port Peripherals.LED2
LED3: U1.4(PE5) ; port Peripherals.LED3
OSC32_IN: R1.2 SB1.1 U1.8(PC14)
OSC32_OUT: R2.2 SB2.1 U1.9(PC15)
OSC_IN: R3.1 SB3.1 SB5.1 U1.23(PH0-OSC_IN)
OSC_OUT: R4.1 SB4.1 U1.24(PH1-OSC_OUT)
PA0: U1.34(PA0)
PA4: U1.40(PA4)
PA6: U1.42(PA6)
PA7: U1.43(PA7)
PA8: U1.100(PA8)
PA9: U1.101(PA9)
PA10: U1.102(PA10)
PA12: U1.104(PA12)
PB0: U1.46(PB0)
PB1: U1.47(PB1)
PB4: U1.134(PB4)
PB6: U1.136(PB6)
PB7: U1.137(PB7)
PB15: U1.76(PB15)
PC2: U1.28(PC2)
PC3: U1.29(PC3)
PC9: U1.99(PC9)
PC10: U1.111(PC10)
PC11: U1.112(PC11)
PC12: U1.113(PC12)
PC14: SB1.2
PC15: SB2.2
PD3: U1.117(PD3)
PD4: U1.118(PD4)
PD7: U1.123(PD7)
PD10: U1.79(PD10)
PD14: U1.85(PD14)
PD15: U1.86(PD15)
PE0: U1.141(PE0)
PE4: U1.3(PE4)
PE8: U1.59(PE8)
PE9: U1.60(PE9)
PE10: U1.63(PE10)
PE11: U1.64(PE11)
PE12: U1.65(PE12)
PE13: U1.66(PE13)
PE14: U1.67(PE14)
PE15: U1.68(PE15)
PF1: U1.11(PF1)
PF2: U1.12(PF2)
PF3: U1.13(PF3)
PF4: U1.14(PF4)
PF5: U1.15(PF5)
PF6: U1.18(PF6)
PF8: U1.20(PF8)
PF9: U1.21(PF9)
PF11: U1.49(PF11)
PF12: U1.50(PF12)
PF13: U1.53(PF13)
PF14: U1.54(PF14)
PF15: U1.55(PF15)
PG0: U1.56(PG0)
PG1: U1.57(PG1)
PG2: U1.87(PG2)
PG3: U1.88(PG3)
PG4: U1.89(PG4)
PG5: U1.90(PG5)
PG6: U1.91(PG6)
PG7: U1.92(PG7)
PG9: U1.124(PG9)
PG10: U1.125(PG10)
PG11: U1.126(PG11)
PG13: U1.128(PG13)
PG15: U1.132(PG15)
PH0: SB3.2
PH1: SB4.2
RESET_MCU: U1.25(NRST) ; port RESET_MCU
RMII.CRS_DV: U1.115(PD1) ; port RMII.CRS_DV
RMII.MDC: U1.27(PC1) ; port RMII.MDC
RMII.MDIO: U1.36(PA2) ; port RMII.MDIO
RMII.REF_CLK: U1.35(PA1) ; port RMII.REF_CLK
RMII.RXD0: U1.44(PC4) ; port RMII.RXD0
RMII.RXD1: U1.45(PC5) ; port RMII.RXD1
RMII.TX_EN: U1.41(PA5) ; port RMII.TX_EN
RMII.TXD0: U1.73(PB12) ; port RMII.TXD0
RMII.TXD1: U1.127(PG12) ; port RMII.TXD1
TRACE.CLK: U1.1(PE2) ; port TRACE.CLK
TRACE.D0: U1.2(PE3) ; port TRACE.D0
TRACE.D1: U1.129(PG14) ; port TRACE.D1
TRACE.D2: U1.116(PD2) ; port TRACE.D2
TRACE.D3: U1.5(PE6) ; port TRACE.D3
UCPD.CC1: U1.74(PB13) ; port UCPD.CC1
UCPD.CC2: U1.75(PB14) ; port UCPD.CC2
UCPD.DBN: U1.140(PB9) ; port UCPD.DBN
UCPD.FLT: U1.139(PB8) ; port UCPD.FLT
UCPD.VBUS_SENSE: U1.103(PA11) ; port UCPD.VBUS_SENSE
USB_HS_N: U1.96(OTG_HSDM) ; port USB_HS_N
USB_HS_P: U1.97(OTG_HSDP) ; port USB_HS_P
USER: U1.7(PC13) ; port Peripherals.USER
XSPI1.CLK: U1.22(PF10) ; port XSPI1.CLK
XSPI1.DQS0: U1.48(PB2) ; port XSPI1.DQS0
XSPI1.IO0: U1.80(PD11) ; port XSPI1.IO0
XSPI1.IO1: U1.81(PD12) ; port XSPI1.IO1
XSPI1.IO2: U1.19(PF7) ; port XSPI1.IO2
XSPI1.IO3: U1.82(PD13) ; port XSPI1.IO3
XSPI1.IO4: U1.58(PE7) ; port XSPI1.IO4
XSPI1.IO5: U1.119(PD5) ; port XSPI1.IO5
XSPI1.IO6: U1.122(PD6) ; port XSPI1.IO6
XSPI1.IO7: U1.26(PC0) ; port XSPI1.IO7
XSPI1.NCLK: U1.135(PB5) ; port XSPI1.NCLK
XSPI1.NCS1: U1.69(PB10) ; port XSPI1.NCS1
XSPI1.NCS2: U1.114(PD0) ; port XSPI1.NCS2
NetC79_2: C79.2 R1.1 X2.2(X2)
NetC81_2: C81.2 R2.1 X2.1(X1)
NetC82_1: C82.1 R4.2 X3.3
NetC83_1: C83.1 R3.2 X3.1

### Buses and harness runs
bus PA[0..15] = port PA[0..15]
bus PB[0..15] = port PB[0..15]
bus PC[0..15] = port PC[0..15]
bus PD[0..15] = port PD[0..15]
bus PE[0..15] = port PE[0..15]
bus PF[0..15] = port PF[0..15]
bus PG[0..15] = port PG[0..15]
bus PH[0..15] = port PH[0..15]

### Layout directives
differential pair; differential pair class DiffPair_90; net class 90 ohms diff: USB_HS_N, USB_HS_P

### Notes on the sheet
- HARNESS
- MCU IOs
- PA5
- PB12
- PG12
- PC4
- PC5
- PD1
- PC1
- PA2
- PA1
- PA13
- PB3
- PA14
- PD8
- PD9
- PA15
- PE2
- PE3
- PG14
- PD2
- PE6
- PB13
- PB14
- PB8
- PB9
- PA11
- (near SB1) 32.768 kHz LSE
- PA3
- PF0
- LSE
- PE5
- PC13
- PD11
- PD12
- PF7
- PD13
- 48MHz HSE
- HSE
- PE7
- PD5
- PD6
- PC0
- PB10
- PD0
- PB2
- PF10
- PB5

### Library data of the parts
C79 C81 = MCD-01781: Capacitor, MLCC, 6.8pF, 50V, C0G/NP0, +/-0.1pF, 0402, T=0.5mm; Part_Preference: Recommended; Manufacturer: YAGEO; Manufacturer_Part_Number: CC0402BRNPO9BN6R8; Component_Country_Of_Origin: China; ShowFields: YES; ID: 3881
C82 C83 = MCD-01775: Capacitor, MLCC, 3.3pF, 50V, NPO, +/-0.1pF, 0402, T=0.5mm; Part_Preference: Recommended; Manufacturer: YAGEO; Manufacturer_Part_Number: CC0402BRNPO9BN3R3; Component_Country_Of_Origin: China; ShowFields: YES; ID: 3875
HW3 = MCD-01015: Socket_IC, LQFP144, IC149 series, pitch 0.5mm, without positionning pin; Part_Preference: Recommended; Manufacturer: YAMAICHI; Manufacturer_Part_Number: IC149-144-145-B5; Component_Country_Of_Origin: Unknown; ShowFields: YES; ID: 3005
R1 R2 = MCD-00052: Resistor, 0R, 0402, +/-5%, 1/16W; Part_Preference: Recommended; Manufacturer: YAGEO; Manufacturer_Part_Number: RC0402JR-070RL; Order_Code_RS: 618-5804; Component_Country_Of_Origin: China; ShowFields: YES; ID: 2540
R3 R4 = MCD-00052: Resistor, 0R, 0402, +/-5%, 1/16W; Manufacturer_Part_Number: RC0402JR-070RL; Manufacturer: YAGEO; Part_Preference: Recommended; Order_Code_RS: 618-5804; Component_Country_Of_Origin: China; ShowFields: YES; ID: 2540
SB1-SB5 = MCD-00071: Solder Bridge ON; Part_Type: Misc; Manufacturer_Part_Number: RC0603JR-070RL; Manufacturer: YAGEO; Part_Preference: Recommended; ShowFields: YES; ID: 2521
TP46 = MCD-00631: as TP45 on sheet Connectors
U1 = MCD-04286: as U1 on sheet MCU_Power
X2 = MCD-02291: Crystal, 32.768kHz, 9pF, +/-20ppm, 70KR, 1.6x1mm; Part_Type: Crystal_Osc; Part_Preference: Recommended; Manufacturer: NDK; Manufacturer_Part_Number: NX1610SE-32.768KHz-EXS00A-MU01499; Component_Country_Of_Origin: Japan; ShowFields: YES; ID: 4391
X3 = MCD-02262: Crystal, 48MHz, 7pF, +/-20 ppm, 80R, 1.6x1.2mm; Part_Type: Crystal_Osc; Part_Preference: Recommended; Manufacturer: NDK; Manufacturer_Part_Number: NX1612SA-48MHZ-EXS00A-CS13734; Component_Country_Of_Origin: Unknown; ShowFields: YES; ID: 4362

## Sheet Power_Sources.SchDoc: Power Sources
size A4; Date: Not used; ApprovedBy: Not used; CheckedBy: Not used; Author: Not used; CompanyName: STMicroelectronics; DrawnBy: Not used; Engineer: Not used; Organization: Not used; Address1: Not used; Address2: Not used; Address3: Not used; Address4: Not used; DocumentNumber: 6; Revision: Not used; SheetNumber: 6; SheetTotal: 14
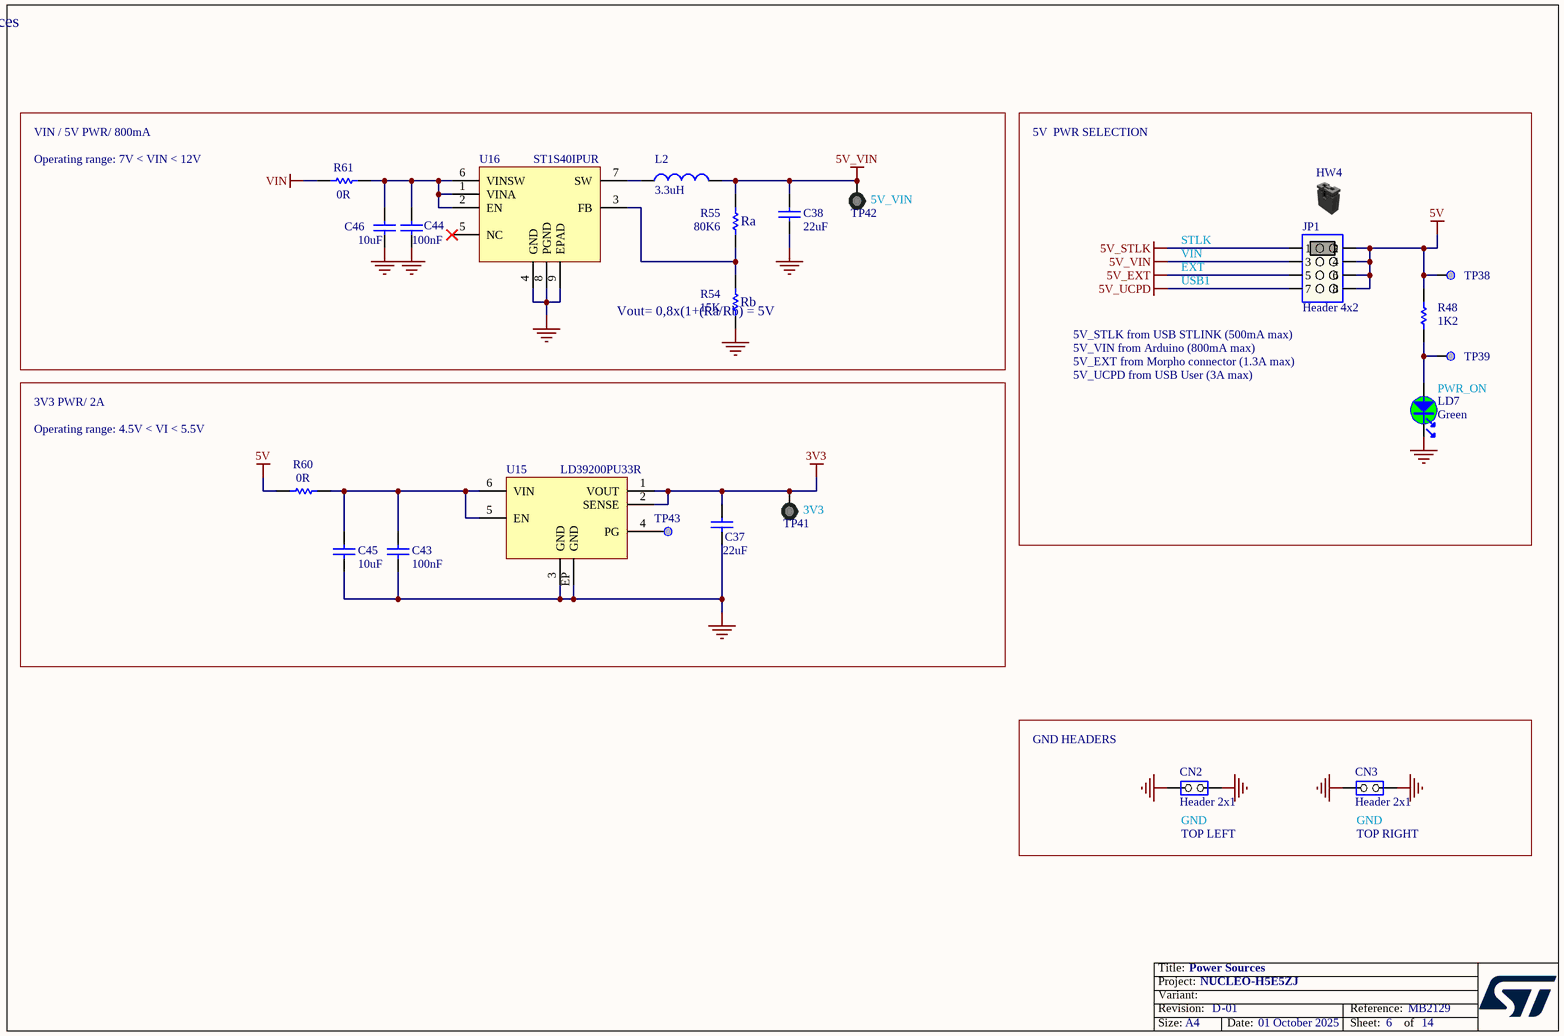
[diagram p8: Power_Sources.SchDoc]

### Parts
C37  value 22uF  [C0603_H0P8]  (hidden comment: Capacitor)
C38  value 22uF  [C0603_H0P8]  (hidden comment: Capacitor)
C43  value 100nF  [C0402]  (hidden comment: Capacitor)
C44  value 100nF  [C0402]  (hidden comment: Capacitor)
C45  value 10uF  [C1206_H1P6]  (hidden comment: Capacitor)
C46  value 10uF  [C1206_H1P6]  (hidden comment: Capacitor)
CN2  value Header 2x1  [CON_SAMTEC_TSW-102-09-X-S]  (hidden comment: Jumper_Header 2x1)
CN3  value Header 2x1  [CON_SAMTEC_TSW-102-09-X-S]  (hidden comment: Jumper_Header 2x1)
HW4  Shunt Black 2.54mm  (value not drawn)  (mechanical)
JP1  value Header 4x2  [CON_SAMTEC_TSW-104-07-X-D]  (hidden comment: Jumper_Header 4x2 Fitted 1-2)
L2  value 3.3uH  [IND_5040_WURTH_74404054033]  (hidden comment: Inductor)
LD7  value Green  [LED_0603_OSRAM_LG-Q396-PS-35_GREEN_1A2K_H0P4]  (hidden comment: LED_green)
R48  value 1K2  [R0402]  (hidden comment: Resistor)
R54  value 15K  [R0402]  (hidden comment: Resistor)
R55  value 80K6  [R0402]  (hidden comment: Resistor)
R60  value 0R  [R0603]  (hidden comment: Resistor)
R61  value 0R  [R0603]  (hidden comment: Resistor)
TP38  Test Point  [TP_SMD_0-6MM]  (value not drawn)  (no BOM)
TP39  Test Point  [TP_SMD_0-6MM]  (value not drawn)  (no BOM)
TP41  Test_Point_PTH_1mm_2mm  [TP_PTH_1MM_2MM]  (value not drawn)  (no BOM)
TP42  Test_Point_PTH_1mm_2mm  [TP_PTH_1MM_2MM]  (value not drawn)  (no BOM)
TP43  Test Point  [TP_SMD_0-6MM]  (value not drawn)  (no BOM)
U15  LD39200PU33R  [ICC_DFN6-EPAD_3X3_P095]
U16  ST1S40IPUR  [ICC_VFQFPN8-EPAD_4X4_P080]

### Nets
3V3: C37.2 TP41.1 U15.1(VOUT) U15.2(SENSE)
5V: JP1.2 JP1.4 JP1.6 JP1.8 R48.2 R60.1 TP38.1
5V_EXT: JP1.5
5V_STLK: JP1.1
5V_UCPD: JP1.7
5V_VIN: C38.2 JP1.3 L2.2 R55.2 TP42.1
GND: C37.1 C38.1 C43.1 C44.1 C45.1 C46.1 CN2.1(COMMON) CN2.2(NO) CN3.1(COMMON) CN3.2(NO) LD7.2 R54.1 U15.3(GND) U15.EP(GND) U16.4(GND) U16.8(PGND) U16.9(EPAD)
VIN: R61.1
NetC43_2: C43.2 C45.2 R60.2 U15.5(EN) U15.6(VIN)
NetC44_2: C44.2 C46.2 R61.2 U16.1(VINA) U16.2(EN) U16.6(VINSW)
NetL2_1: L2.1 U16.7(SW)
NetLD7_1: LD7.1 R48.1 TP39.1
NetR54_2: R54.2 R55.1 U16.3(FB)
NetTP43_1: TP43.1 U15.4(PG)

Not connected (* = marked no-connect by the designer): U16 5(NC)*

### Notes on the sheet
- VIN / 5V PWR/ 800mA
- Operating range: 7V < VIN < 12V
- 5V  PWR SELECTION
- (near R55) Ra
- (near TP42) 5V_VIN
- STLK
- (near R54) Rb
- (near R54) Vout= 0,8x(1+(Ra/Rb) = 5V
- VIN
- EXT
- USB1
- (near JP1) 5V_STLK from USB STLINK (500mA max)
- 5V_VIN from Arduino (800mA max)
- 5V_EXT from Morpho connector (1.3A max)
- 5V_UCPD from USB User (3A max)
- 3V3 PWR/ 2A
- Operating range: 4.5V < VI < 5.5V
- (near LD7) PWR_ON
- (near TP41) 3V3
- GND HEADERS
- (near CN2) GND
- (near CN2) TOP LEFT
- (near CN3) GND
- (near CN3) TOP RIGHT

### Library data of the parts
C37 C38 = MCD-02607: Capacitor, MLCC, 22uF, 10V, X5R, +/-20%, 0603, T=0.8mm; Part_Preference: Recommended; Manufacturer: YAGEO; Manufacturer_Part_Number: CC0603MRX5R6BB226; Order_Code_RS: 2006627; Component_Country_Of_Origin: Taiwan°; ShowFields: YES; ID: 4713
C43 C44 = MCD-00006: as C69 on sheet MCU_Power
C45 C46 = MCD-02610: Capacitor, MLCC, 10uF, 25V, X5R, +/-10%, 1206, T=1.6mm; Part_Preference: Recommended; Manufacturer: YAGEO; Manufacturer_Part_Number: CC1206KKX5R8BB106; Partial_Alternate_Internal_Part_Number: MCD-04187; Order_Code_RS: 1991983; ShowFields: YES; ID: 4716; Component_Country_Of_Origin: China
CN2 CN3 = MCD-00214: Header, 2x1, 2.54mm, VR, TH, T=5.84mm/10.16mm; Part_Type: Connector; Part_Preference: Recommended; Manufacturer: SAMTEC; Manufacturer_Part_Number: TSW-102-09-G-S; Full_Alternate_Internal_Part_Number: MCD-02393; Partial_Alternate_Internal_Part_Number: MCD-03591, MCD-03719, MCD-04227; Order_Code_RS: 180-3129; Component_Country_Of_Origin: China, Costa Rica, Malaysia, USA, Vietnam; ShowFields: YES; ID: 2652
HW4 = MCD-00043: Shunt, 2.54mm, Black, 4.3A, 6.1mm, 5mR; Manufacturer_Part_Number: SNT-100-BK-G; Manufacturer: SAMTEC; Part_Type: Misc; Part_Preference: Recommended; Manufacturer_HQ_COO: Unknown; Full_Alternate_Internal_Part_Number: MCD-02388; Partial_Alternate_Internal_Part_Number: MCD-01849, MCD-01864; Value: SNT-100-BK-G; Order_Code_RS: 158-7784; Component_Country_Of_Origin: China, Costa Rica, Malaysia, USA, Vietnam; Alternate_EMS: A; ShowFields: YES; ID: 2551
JP1 = MCD-01910: Header, 4x2, 2.54mm, VR, TH, T=5.84mm/2.54mm; Part_Type: Connector; Part_Preference: Recommended; Manufacturer: SAMTEC; Manufacturer_Part_Number: TSW-104-07-G-D; Partial_Alternate_Internal_Part_Number: MCD-04191; Order_Code_RS: 161-2260; Component_Country_Of_Origin: China, Costa Rica, Malaysia, USA, Vietnam; ShowFields: YES; ID: 4010
L2 = MCD-02220: Inductor, 3.3uH, +/-30%, 3.4A, 24mR, 5040, T=4mm; Part_Preference: Recommended; Manufacturer: WURTH ELEKTRONIK; Manufacturer_Part_Number: 74404054033; Order_Code_RS: 814-2571; Component_Country_Of_Origin: Unknown; ShowFields: YES; ID: 4320
LD7 = MCD-02901: LED, Green, 2V, 20mA, 0603; Part_Type: Display; Part_Preference: Recommended; Manufacturer: EVERLIGHT; Manufacturer_Part_Number: 19-217/G7C-AN1P2/6T; Partial_Alternate_Internal_Part_Number: MCD-02400, MCD-00588; Component_Country_Of_Origin: China; ShowFields: YES; ID: 5017
R48 = MCD-00373: Resistor, 1K2, 0402, +/-1%, 1/16W; Part_Preference: Recommended; Manufacturer: YAGEO; Manufacturer_Part_Number: RC0402FR-071K2L; Component_Country_Of_Origin: China; ShowFields: YES; ID: 2906
R54 = MCD-02570: Resistor, 15K, 0402, +/-0.1%, 1/16W, +/-25ppm/°C; Part_Preference: Recommended; Manufacturer: YAGEO; Manufacturer_Part_Number: RT0402BRD0715KL; Order_Code_RS: 1991284; Component_Country_Of_Origin: China; ShowFields: YES; ID: 4676
R55 = MCD-03683: Resistor, 80K6, 0402, +/-0.1%, 1/16W, +/-25ppm/°C; Part_Preference: Recommended; Manufacturer: YAGEO; Manufacturer_Part_Number: RT0402BRD0780K6L; ShowFields: YES; ID: 5799; Component_Country_Of_Origin: Taiwan
R60 R61 = MCD-00181: as R62 on sheet MCU_Power
TP38 TP39 TP43 = MCD-00631: as TP45 on sheet Connectors
TP41 TP42 = MCD-01506: Test Point trought hole 1mm/2mm; Part_Type: Misc; Part_Preference: Recommended; ShowFields: YES; ID: 3606
U15 = MCD-03923: LDO, 3V3, 2A, Ultra low drop and low noise voltage regulator; Part_Type: IC; Part_Preference: Not recommended; Manufacturer: STMICROELECTRONICS; Component_Country_Of_Origin: China; ShowFields: YES; ID: 6039
U16 = MCD-02219: Regulator, 3A, DC step-down switching; Part_Type: IC; Part_Preference: Recommended; Manufacturer: STMICROELECTRONICS; Manufacturer_HQ_COO: EU; Component_Country_Of_Origin: Malaysia; ShowFields: YES; ID: 4319

## Sheet Peripherals.SchDoc: Peripherals
size A4; Date: Not used; ApprovedBy: Not used; CheckedBy: Not used; Author: Not used; CompanyName: STMicroelectronics; DrawnBy: Not used; Engineer: Not used; Organization: Not used; Address1: Not used; Address2: Not used; Address3: Not used; Address4: Not used; DocumentNumber: 7; Revision: Not used; SheetNumber: 7; SheetTotal: 14
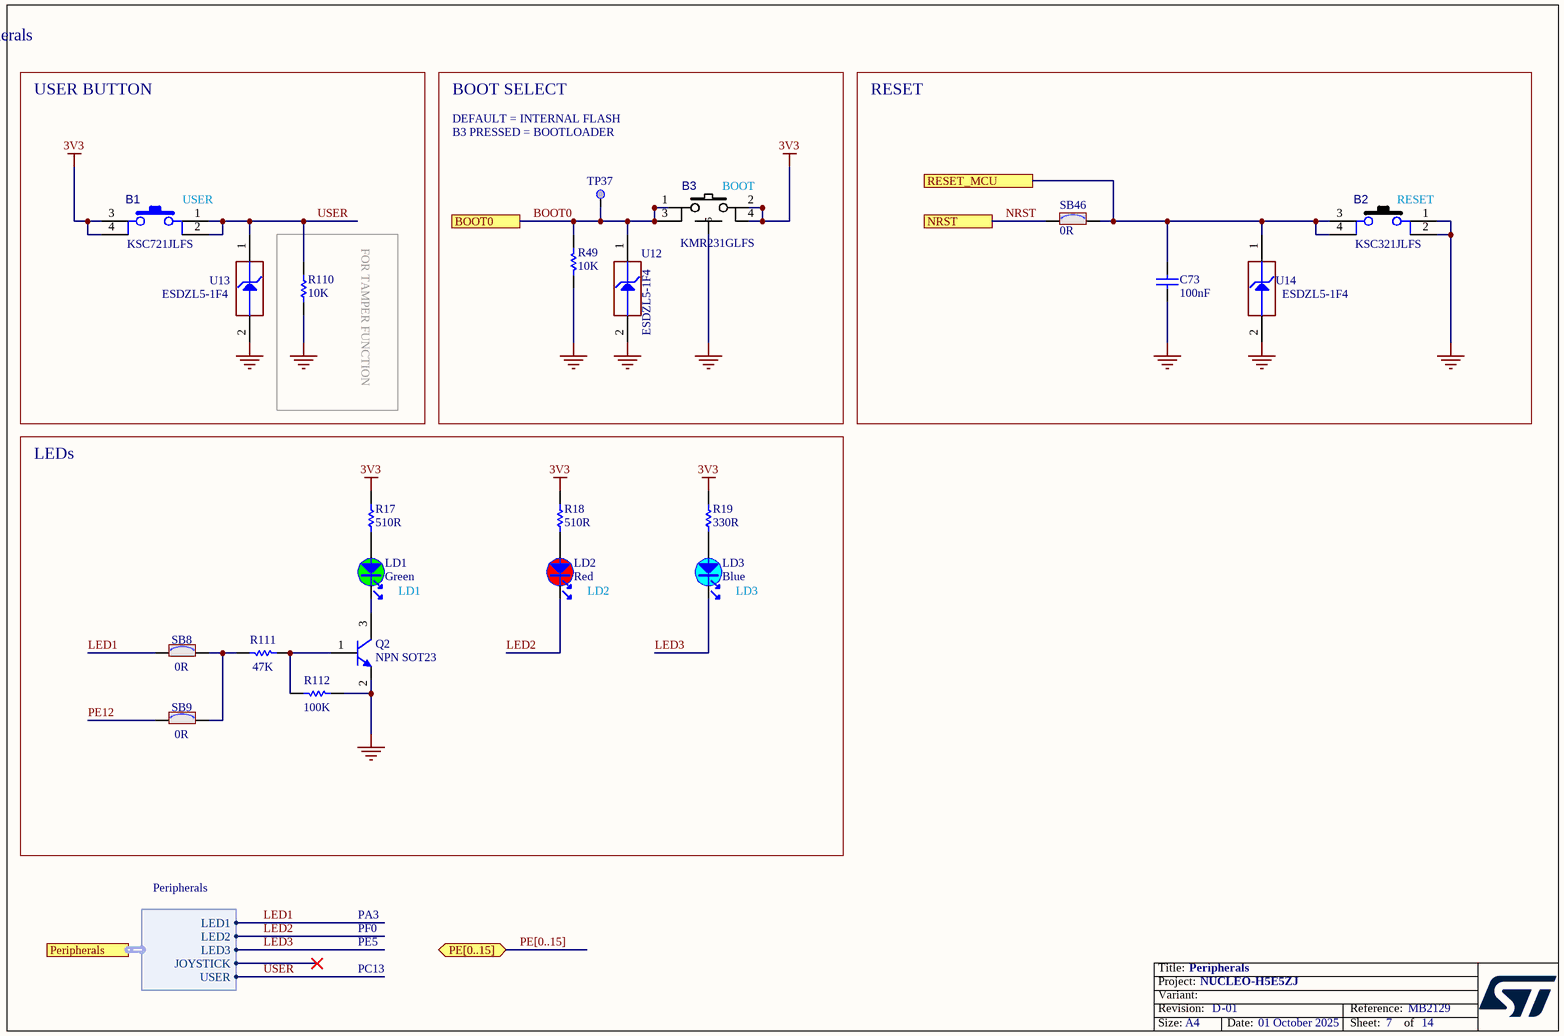
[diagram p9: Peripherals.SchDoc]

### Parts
B1  value KSC721JLFS  [SWI_C&K_KSC721JLFS_BLUE]  (hidden comment: SW_BLUE_KSC721JLFS)
B2  value KSC321JLFS  [SWI_C&K_KSC321JLFS_BLACK]  (hidden comment: SW_BLACK_KSC321JLFS)
B3  value KMR231GLFS  [SWI_C&K_Y78B23110FP__ITT_KMR231GLFS]  (hidden comment: SW-PUSH-CMS_KMR2_BLACK)
C73  value 100nF  [C0402]  (hidden comment: Capacitor)
LD1  value Green  [LED_0603_OSRAM_LG-Q396-PS-35_GREEN_1A2K_H0P4]  (hidden comment: LED_green)
LD2  value Red  [LED_0603_RED]  (hidden comment: LED_red)
LD3  value Blue  [LED_0603_SMD-B_BLUE_H0P4]  (hidden comment: LED_blue)
Q2  value NPN SOT23  [NPN_SOT23]  (hidden comment: 9013-SOT23)
R17  value 510R  [R0402]  (hidden comment: Resistor)
R18  value 510R  [R0402]  (hidden comment: Resistor)
R19  value 330R  [R0402]  (hidden comment: Resistor)
R49  value 10K  [R0402]  (hidden comment: Resistor)
R110  value 10K  [R0402]  (hidden comment: Resistor)
R111  value 47K  [R0603]  (hidden comment: Resistor)
R112  value 100K  [R0402]  (hidden comment: Resistor)
SB8  value 0R  [SOLDER-BRIDGE_R0603-0R]  (hidden comment: SB_ON)
SB9  value 0R  [SOLDER-BRIDGE_R0603-0R]  (hidden comment: SB_ON)
SB46  value 0R  [SOLDER-BRIDGE_R0402-0R]  (hidden comment: SB_ON)
TP37  Test Point  [TP_SMD_0-6MM]  (value not drawn)  (no BOM)
U12  value ESDZL5-1F4  [ESD_0201_H0P3_1K_2A]  (hidden comment: ESD-TRANSIL)
U13  value ESDZL5-1F4  [ESD_0201_H0P3_1K_2A]  (hidden comment: ESD-TRANSIL)
U14  value ESDZL5-1F4  [ESD_0201_H0P3_1K_2A]  (hidden comment: ESD-TRANSIL)

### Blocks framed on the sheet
USER BUTTON: B1 U13
BOOT SELECT: B3 R49 TP37 U12
RESET: B2 C73 SB46 U14
FOR TAMPER FUNCTION: R110
LEDs: LD1-LD3 Q2 R17-R19 R111 R112 SB8 SB9

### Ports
BOOT0, NRST, PE[0..15] (bidir), Peripherals (harness Peripherals), RESET_MCU

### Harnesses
Peripherals: LED1, LED2, USER, LED3, JOYSTICK

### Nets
3V3: B1.3 B1.4 B3.2 B3.4 R17.2 R18.2 R19.2
GND: B2.1 B2.2 B3.5 C73.1 Q2.2(E) R49.1 R110.1 R112.2 U12.2(GND) U13.2(GND) U14.2(GND)
BOOT0: B3.1 B3.3 R49.2 TP37.1 U12.1(IO1) ; port BOOT0
LED1: SB8.1 ; port Peripherals.LED1
LED2: LD2.2 ; port Peripherals.LED2
LED3: LD3.2 ; port Peripherals.LED3
NRST: SB46.2 ; port NRST
PE12: SB9.1
RESET_MCU: B2.3 B2.4 C73.2 SB46.1 U14.1(IO1) ; port RESET_MCU
USER: B1.1 B1.2 R110.2 U13.1(IO1) ; port Peripherals.USER
NetLD1_1: LD1.1 R17.1
NetLD1_2: LD1.2 Q2.3(C)
NetLD2_1: LD2.1 R18.1
NetLD3_1: LD3.1 R19.1
NetQ2_1: Q2.1(B) R111.2 R112.1
NetR111_1: R111.1 SB8.2 SB9.2

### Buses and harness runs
bus PE[0..15] = port PE[0..15]

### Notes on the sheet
- DEFAULT = INTERNAL FLASH
- B3 PRESSED = BOOTLOADER
- (near B1) USER
- (near B3) BOOT
- (near B2) RESET
- (near LD1) LD1
- (near LD2) LD2
- (near LD3) LD3
- PA3
- PF0
- PE5
- PC13

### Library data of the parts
B1 = MCD-01800: Switch tactile, SPST-NO, 32V, 50mA, 6.2x6.2mm; Part_Type: Misc; Part_Preference: Recommended; Manufacturer: C&K; Partial_Alternate_Internal_Part_Number: MCD-03151; Manufacturer_HQ_COO: Unknown; Component_Country_Of_Origin: France; ShowFields: YES; ID: 3900
B2 = MCD-01799: Switch tactile, SPST-NO, 32V, 50mA, 6.2x6.2mm; Part_Type: Misc; Part_Preference: Recommended; Manufacturer: C&K; Manufacturer_HQ_COO: Unknown; Order_Code_RS: 894-9091; Component_Country_Of_Origin: France; ShowFields: YES; ID: 3899
B3 = MCD-01485: Switch tactile, SPST-NO, 32V, 50mA, 2.8x4.6mm; Part_Type: Misc; Part_Preference: Recommended; Manufacturer: C&K; Manufacturer_HQ_COO: Unknown; Order_Code_RS: 505-9192; Component_Country_Of_Origin: France; ShowFields: YES; ID: 3585
C73 = MCD-00006: as C69 on sheet MCU_Power
LD1 = MCD-02901: as LD7 on sheet Power_Sources
LD2 = MCD-02899: LED, Red, 2V35, 20mA, 0603; Part_Type: Display; Part_Preference: Recommended; Manufacturer: EVERLIGHT; Manufacturer_Part_Number: 19-213/R6C-AP1Q2B/5T; Full_Alternate_Internal_Part_Number: MCD-00049; Component_Country_Of_Origin: China; ShowFields: YES; ID: 5015
LD3 = MCD-02786: LED, Blue, 2.5V to 3.1V, 10mA, 0603; Part_Type: Display; Part_Preference: Recommended; Manufacturer: EVERLIGHT; Manufacturer_Part_Number: 19-217/BHC-ZL1M2RY/6T; Full_Alternate_Internal_Part_Number: MCD-01131; Component_Country_Of_Origin: China; ShowFields: YES; ID: 4898
Q2 = MCD-00073: NPN Bipolar Transistor; Part_Type: IC; Manufacturer_Part_Number: BSR14; Manufacturer: ON SEMICONDUCTOR; Part_Preference: Recommended; Component_Country_Of_Origin: Unknown; ShowFields: YES; ID: 2519
R17 R18 = MCD-00064: Resistor, 510R, 0402, +/-1%, 1/16W; Part_Preference: Recommended; Manufacturer: YAGEO; Manufacturer_Part_Number: RC0402FR-07510RL; Order_Code_RS: 1458804; Component_Country_Of_Origin: China; ShowFields: YES; ID: 2525
R19 = MCD-00062: Resistor, 330R, 0402, +/-1%, 1/16W; Part_Preference: Recommended; Manufacturer: YAGEO; Manufacturer_Part_Number: RC0402FR-07330RL; Order_Code_RS: 9239170; Component_Country_Of_Origin: China; ShowFields: YES; ID: 2529
R49 R110 = MCD-00053: Resistor, 10K, 0402, +/-1%, 1/16W; BMS_Part_Number: 9131590; Part_Preference: Recommended; Manufacturer: YAGEO; Manufacturer_Part_Number: RC0402FR-0710KL; Order_Code_RS: 9239359; Component_Country_Of_Origin: China; ShowFields: YES; ID: 2539
R111 = MCD-00222: Resistor, 47K, 0603, 1%, 1/10W; Manufacturer_Part_Number: RC0603FR-0747KL; Manufacturer: YAGEO; Part_Preference: Recommended; Component_Country_Of_Origin: China; ShowFields: YES; ID: 2645
R112 = MCD-00059: Resistor, 100K, 0402, +/-1%, 1/16W; Part_Preference: Recommended; Manufacturer: YAGEO; Manufacturer_Part_Number: RC0402FR-07100KL; Partial_Alternate_Internal_Part_Number: MCD-03301; Component_Country_Of_Origin: China; ShowFields: YES; ID: 2533; Alternate_EMS: M
SB8 SB9 = MCD-00071: as SB6 on sheet Connectors
SB46 = MCD-01618: as SB45 on sheet MCU_Power
TP37 = MCD-00631: as TP45 on sheet Connectors
U12-U14 = MCD-03501: Diode, ESD TVS, 5V5, 100nA, 10V, 0201; Manufacturer: STMICROELECTRONICS; Part_Preference: Recommended; Component_Country_Of_Origin: Singapore; ShowFields: YES; ID: 5617

## Sheet M2_SerMem_Connector.SchDoc: M2_SERIAL-MEMORY_CONNECTOR
size A4; Date: Not used; ApprovedBy: Not used; CheckedBy: Not used; Author: Not used; CompanyName: STMicroelectronics; DrawnBy: Not used; Engineer: Not used; Organization: Not used; Address1: Not used; Address2: Not used; Address3: Not used; Address4: Not used; DocumentNumber: 9; Revision: Not used; SheetNumber: 9; SheetTotal: 14
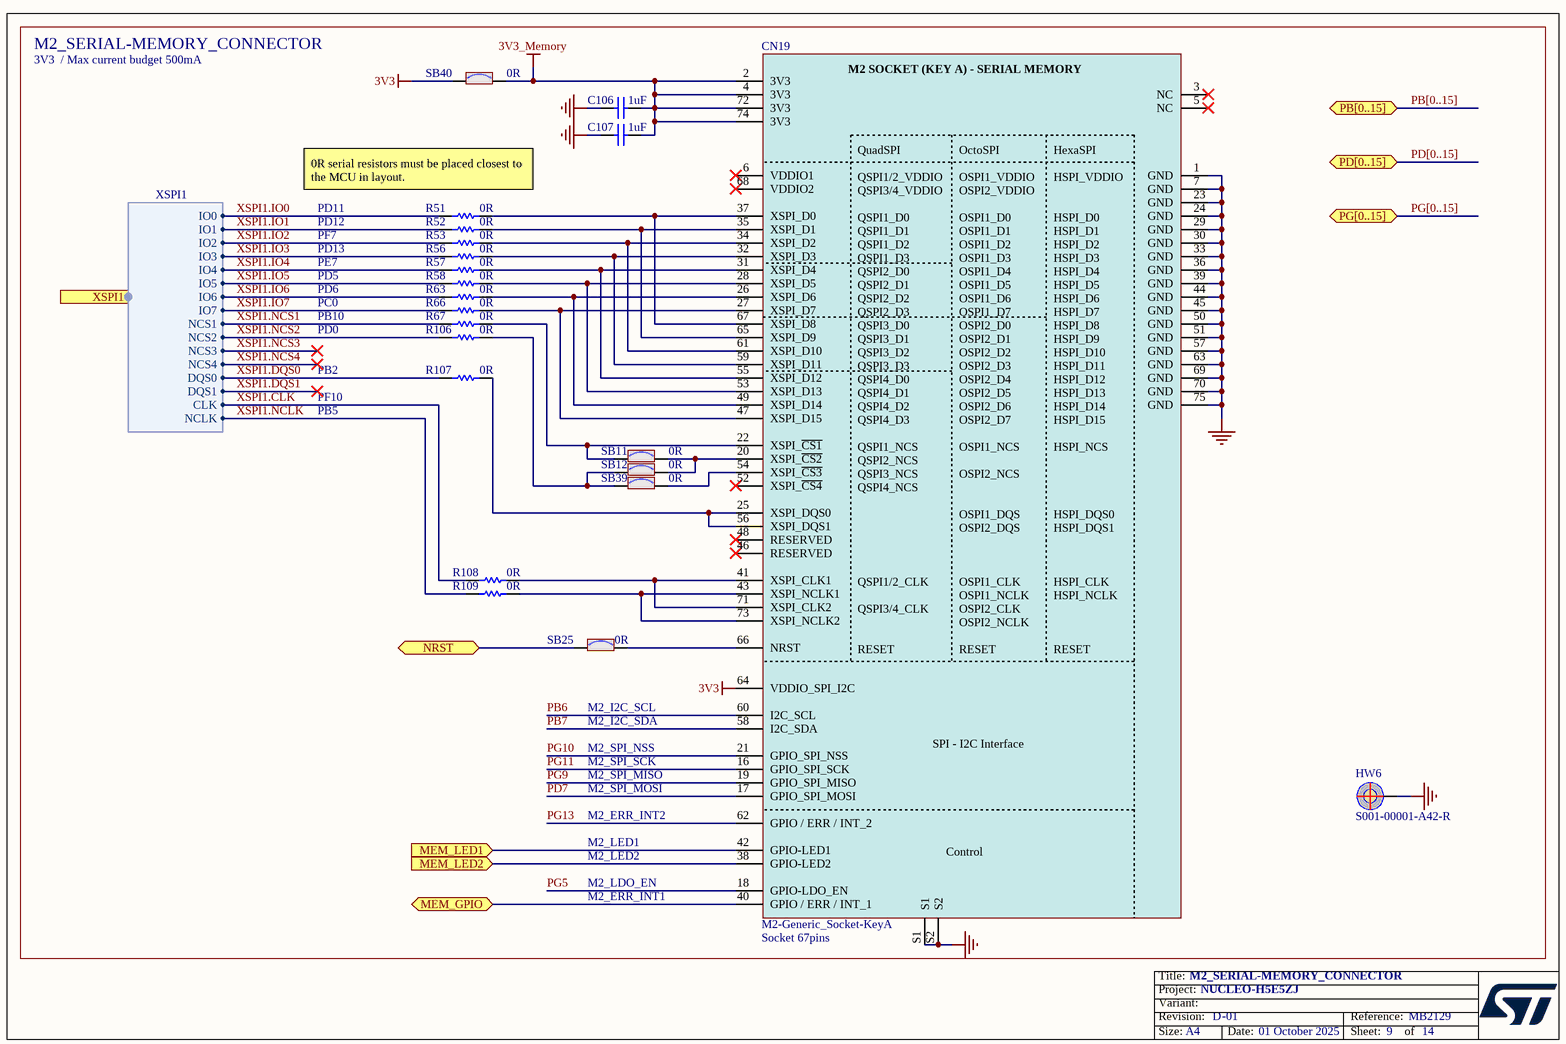
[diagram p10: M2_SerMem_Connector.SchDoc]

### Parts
C106  value 1uF  [C0402]  (hidden comment: Capacitor)
C107  value 1uF  [C0402]  (hidden comment: Capacitor)
CN19  M2-Generic_Socket-KeyA  value Socket 67pins  [CON_AMPHENOL_MDT-420-A-03001]
HW6  value S001-00001-A42-R  [MISC_REGO_S001_00001_A42_R]  (hidden comment: M2_POSITION_HOLE)
R51  value 0R  [R0603]  (hidden comment: Resistor)
R52  value 0R  [R0603]  (hidden comment: Resistor)
R53  value 0R  [R0603]  (hidden comment: Resistor)
R56  value 0R  [R0603]  (hidden comment: Resistor)
R57  value 0R  [R0603]  (hidden comment: Resistor)
R58  value 0R  [R0603]  (hidden comment: Resistor)
R63  value 0R  [R0603]  (hidden comment: Resistor)
R66  value 0R  [R0603]  (hidden comment: Resistor)
R67  value 0R  [R0603]  (hidden comment: Resistor)
R106  value 0R  [R0603]  (hidden comment: Resistor)
R107  value 0R  [R0603]  (hidden comment: Resistor)
R108  value 0R  [R0603]  (hidden comment: Resistor)
R109  value 0R  [R0603]  (hidden comment: Resistor)
SB11  value 0R  [SOLDER-BRIDGE_R0603-0R]  (hidden comment: SB_ON)
SB12  value 0R  [SOLDER-BRIDGE_R0603-0R]  (hidden comment: SB_ON)
SB25  value 0R  [SOLDER-BRIDGE_R0603-0R]  (hidden comment: SB_ON)
SB39  value 0R  [SOLDER-BRIDGE_R0603-0R]  (hidden comment: SB_ON)
SB40  value 0R  [SOLDER-BRIDGE_R0603-0R]  (hidden comment: SB_ON)

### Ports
MEM_GPIO (bidir), MEM_LED1 (in), MEM_LED2 (in), NRST (bidir), PB[0..15] (bidir), PD[0..15] (bidir), PG[0..15] (bidir), XSPI1 (harness XSPI1)

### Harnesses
XSPI1: IO0, IO1, IO2, IO3, IO4, IO5, IO6, IO7, NCS1, NCS2, DQS0, CLK, NCLK, NCS3, NCS4, DQS1

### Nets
3V3: CN19.64(VDDIO_SPI_I2C) SB40.2
3V3_Memory: C106.2 C107.2 CN19.2(3V3) CN19.4(3V3) CN19.72(3V3) CN19.74(3V3) SB40.1
GND: C106.1 C107.1 CN19.1(GND) CN19.7(GND) CN19.23(GND) CN19.24(GND) CN19.29(GND) CN19.30(GND) CN19.33(GND) CN19.36(GND) CN19.39(GND) CN19.44(GND) CN19.45(GND) CN19.50(GND) CN19.51(GND) CN19.57(GND) CN19.63(GND) CN19.69(GND) CN19.70(GND) CN19.75(GND) CN19.S1 CN19.S2 HW6.1
MEM_GPIO: CN19.40(GPIO_/_ERR_/_INT_1) ; port MEM_GPIO
MEM_LED1: CN19.42(GPIO-LED1) ; port MEM_LED1
MEM_LED2: CN19.38(GPIO-LED2) ; port MEM_LED2
NRST: SB25.2 ; port NRST
PB6: CN19.60(I2C_SCL)
PB7: CN19.58(I2C_SDA)
PD7: CN19.17(GPIO_SPI_MOSI)
PG5: CN19.18(GPIO-LDO_EN)
PG9: CN19.19(GPIO_SPI_MISO)
PG10: CN19.21(GPIO_SPI_NSS)
PG11: CN19.16(GPIO_SPI_SCK)
PG13: CN19.62(GPIO_/_ERR_/_INT_2)
XSPI1.CLK: R108.1 ; port XSPI1.CLK
XSPI1.DQS0: R107.1 ; port XSPI1.DQS0
XSPI1.IO0: R51.1 ; port XSPI1.IO0
XSPI1.IO1: R52.1 ; port XSPI1.IO1
XSPI1.IO2: R53.1 ; port XSPI1.IO2
XSPI1.IO3: R56.1 ; port XSPI1.IO3
XSPI1.IO4: R57.1 ; port XSPI1.IO4
XSPI1.IO5: R58.1 ; port XSPI1.IO5
XSPI1.IO6: R63.1 ; port XSPI1.IO6
XSPI1.IO7: R66.1 ; port XSPI1.IO7
XSPI1.NCLK: R109.1 ; port XSPI1.NCLK
XSPI1.NCS1: R67.1 ; port XSPI1.NCS1
XSPI1.NCS2: R106.1 ; port XSPI1.NCS2
NetCN19_20: CN19.20(XSPI_~{CS2}) SB11.1 SB12.1
NetCN19_22: CN19.22(XSPI_~{CS1}) R67.2 SB11.2
NetCN19_25: CN19.25(XSPI_DQS0) CN19.56(XSPI_DQS1) R107.2
NetCN19_26: CN19.26(XSPI_D6) CN19.49(XSPI_D14) R63.2
NetCN19_27: CN19.27(XSPI_D7) CN19.47(XSPI_D15) R66.2
NetCN19_28: CN19.28(XSPI_D5) CN19.53(XSPI_D13) R58.2
NetCN19_31: CN19.31(XSPI_D4) CN19.55(XSPI_D12) R57.2
NetCN19_32: CN19.32(XSPI_D3) CN19.59(XSPI_D11) R56.2
NetCN19_34: CN19.34(XSPI_D2) CN19.61(XSPI_D10) R53.2
NetCN19_35: CN19.35(XSPI_D1) CN19.65(XSPI_D9) R52.2
NetCN19_37: CN19.37(XSPI_D0) CN19.67(XSPI_D8) R51.2
NetCN19_41: CN19.41(XSPI_CLK1) CN19.71(XSPI_CLK2) R108.2
NetCN19_43: CN19.43(XSPI_NCLK1) CN19.73(XSPI_NCLK2) R109.2
NetCN19_54: CN19.54(XSPI_~{CS3}) SB39.1
NetCN19_66: CN19.66(NRST) SB25.1
NetR106_2: R106.2 SB12.2 SB39.2

Not connected (* = marked no-connect by the designer): CN19 3(NC)* 5(NC)* 6(VDDIO1)* 46(RESERVED)* 48(RESERVED)* 52(XSPI_~{CS4})* 68(VDDIO2)*

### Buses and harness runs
bus PB[0..15] = port PB[0..15]
bus PD[0..15] = port PD[0..15]
bus PG[0..15] = port PG[0..15]

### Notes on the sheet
- 3V3  / Max current budget 500mA
- 0R serial resistors must be placed closest to the MCU in layout.
- PD11
- PD12
- PF7
- PD13
- PE7
- PD5
- PD6
- PC0
- PB10
- PD0
- PB2
- PF10
- PB5
- M2_I2C_SCL
- M2_I2C_SDA
- M2_SPI_SCK
- M2_SPI_NSS
- M2_SPI_MOSI
- M2_SPI_MISO
- M2_ERR_INT2
- M2_LED1
- M2_LED2
- M2_LDO_EN
- M2_ERR_INT1

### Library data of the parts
C106 C107 = MCD-01722: as C50 on sheet MCU_Power
CN19 = MCD-03856: Socket_M2_NGFF, Gen3, 67pins, keyA, RA, SMD, 4.2mm, plating Gold Flash; Part_Type: Connector; Part_Preference: Recommended; Manufacturer: AMPHENOL CS; Manufacturer_Part_Number: MDT420A03001; Component_Country_Of_Origin: Unknown; ShowFields: YES; ID: 5972
HW6 = MCD-03863: NGFF Standoff, Brass, For M2 connector 4.2mm, diameter 5.5 / 4 and screw M3x3.7; Part_Type: Misc; Part_Preference: Recommended; Manufacturer: REGO ELECTRONICS INC; Partial_Alternate_Internal_Part_Number: MCD-04224; ShowFields: YES; ID: 5979; Component_Country_Of_Origin: Taiwan
R51-R53 R56-R58 R63 R66 R67 R106-R109 = MCD-00056: as R99 on sheet MCU_Power
SB11 SB12 SB25 SB39 SB40 = MCD-00071: as SB6 on sheet Connectors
